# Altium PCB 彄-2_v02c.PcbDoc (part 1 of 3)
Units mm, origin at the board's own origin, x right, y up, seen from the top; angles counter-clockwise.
Board outline 115 x 70 mm, 4 copper layers (Top Layer, Mid-Layer 1, Mid-Layer 2, Bottom Layer), stack 1.49 mm thick; 312 components, 169 nets, 916 pads, 492 vias.
Unrouted connection lines stored in the file: 1.
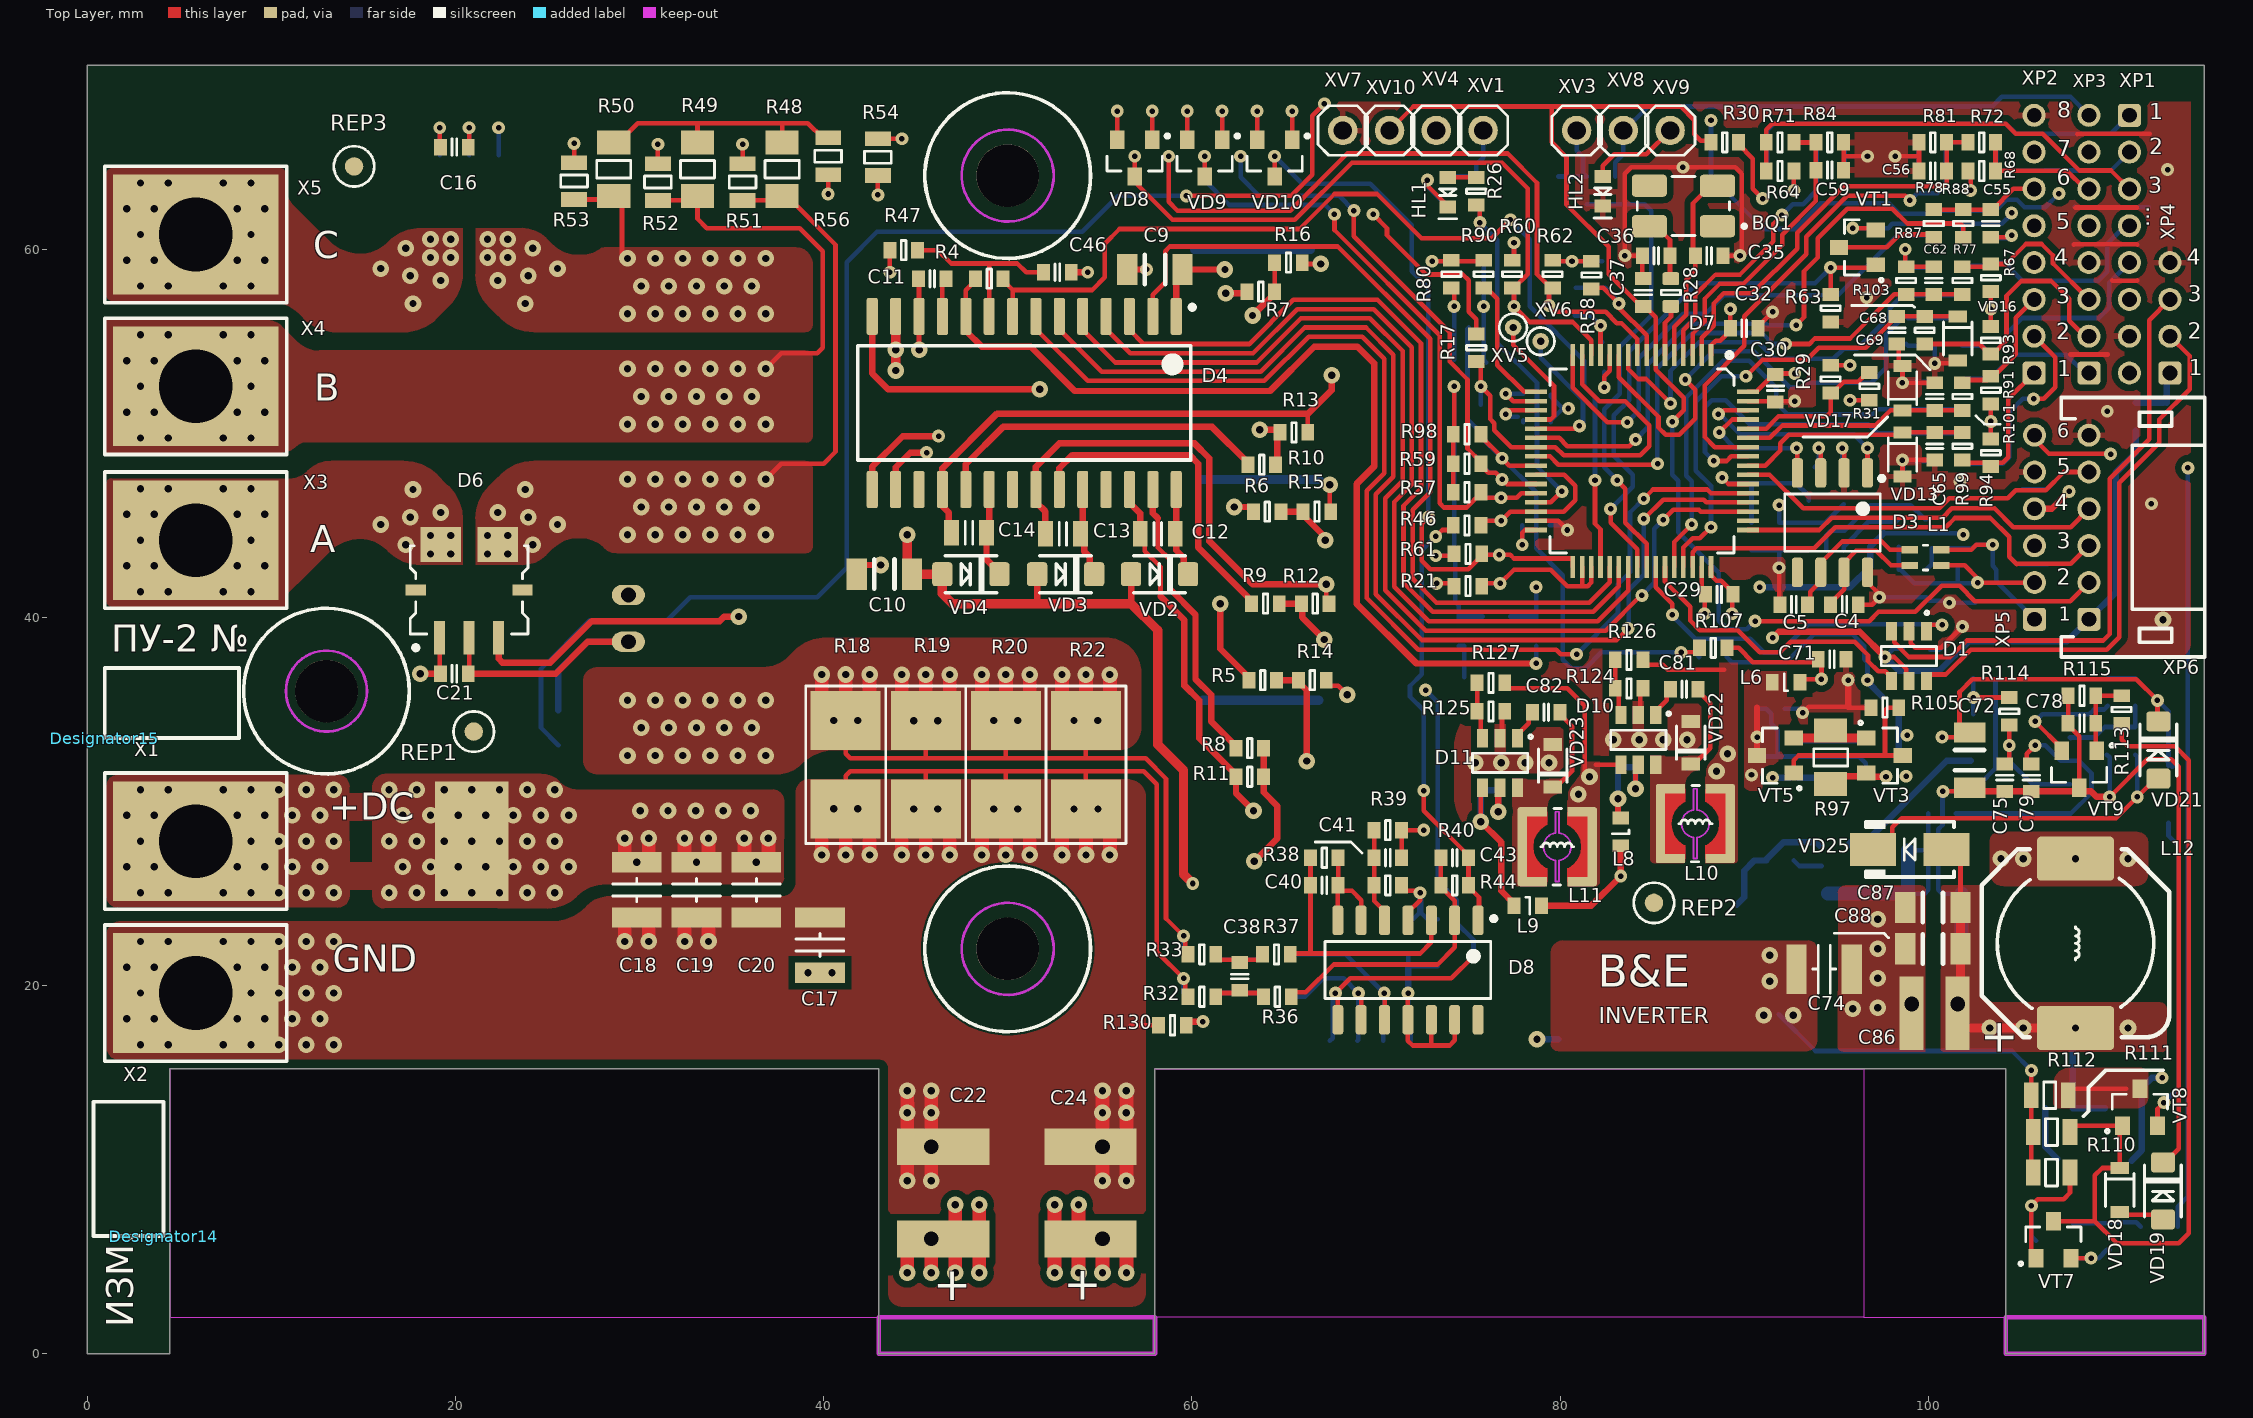
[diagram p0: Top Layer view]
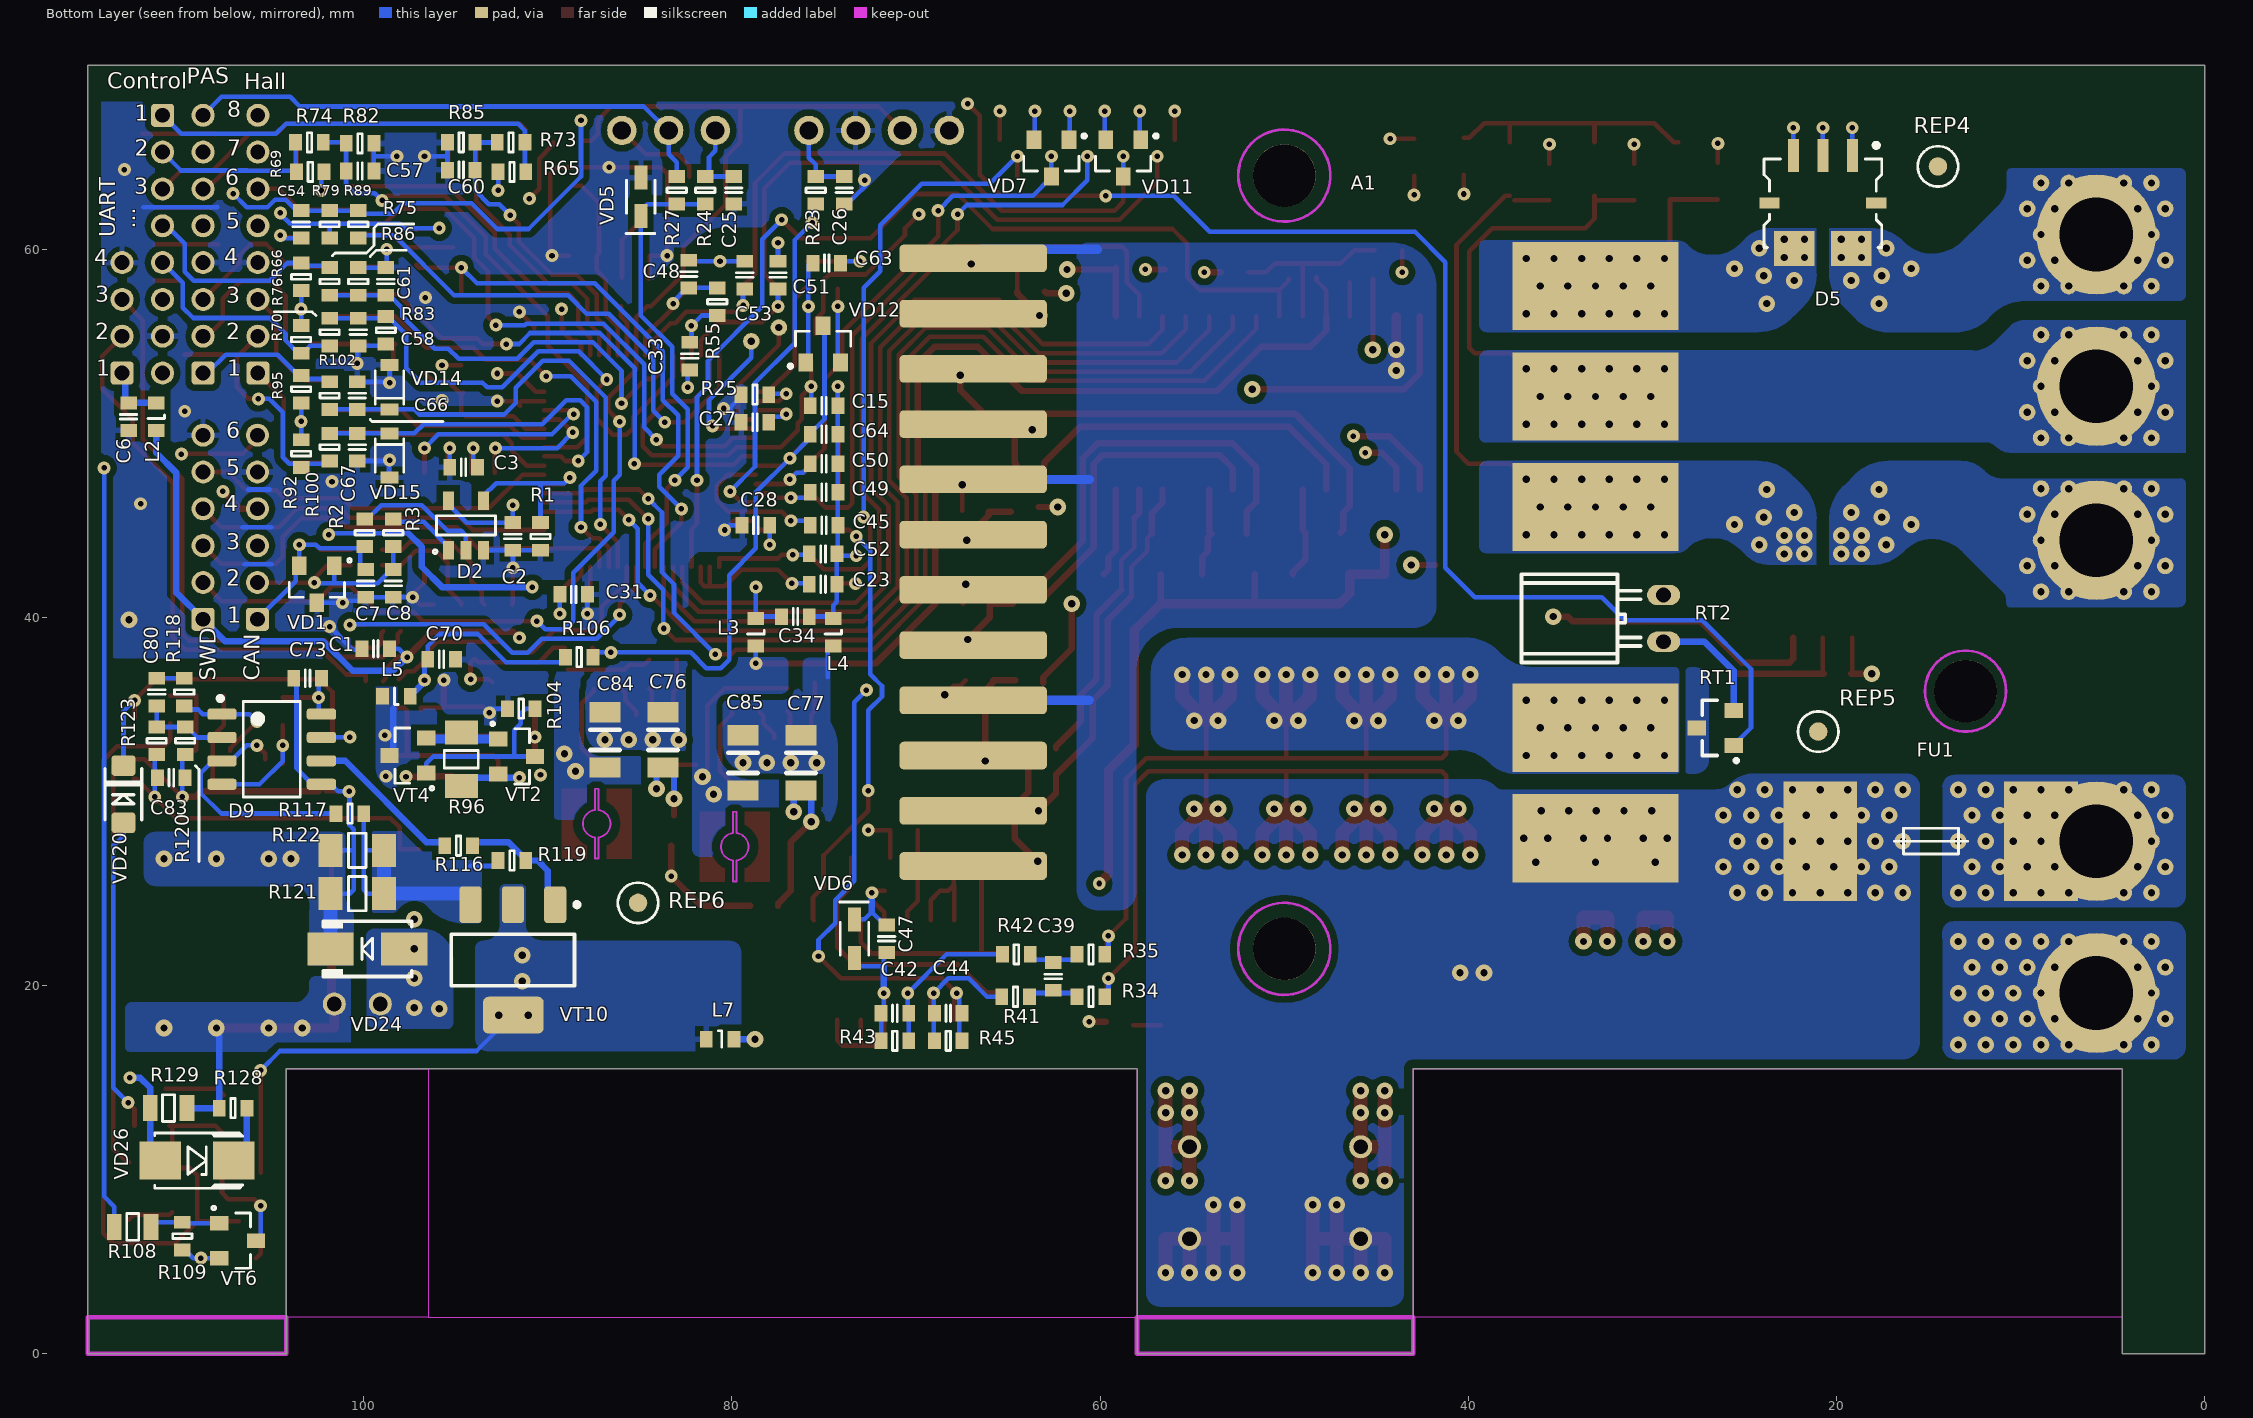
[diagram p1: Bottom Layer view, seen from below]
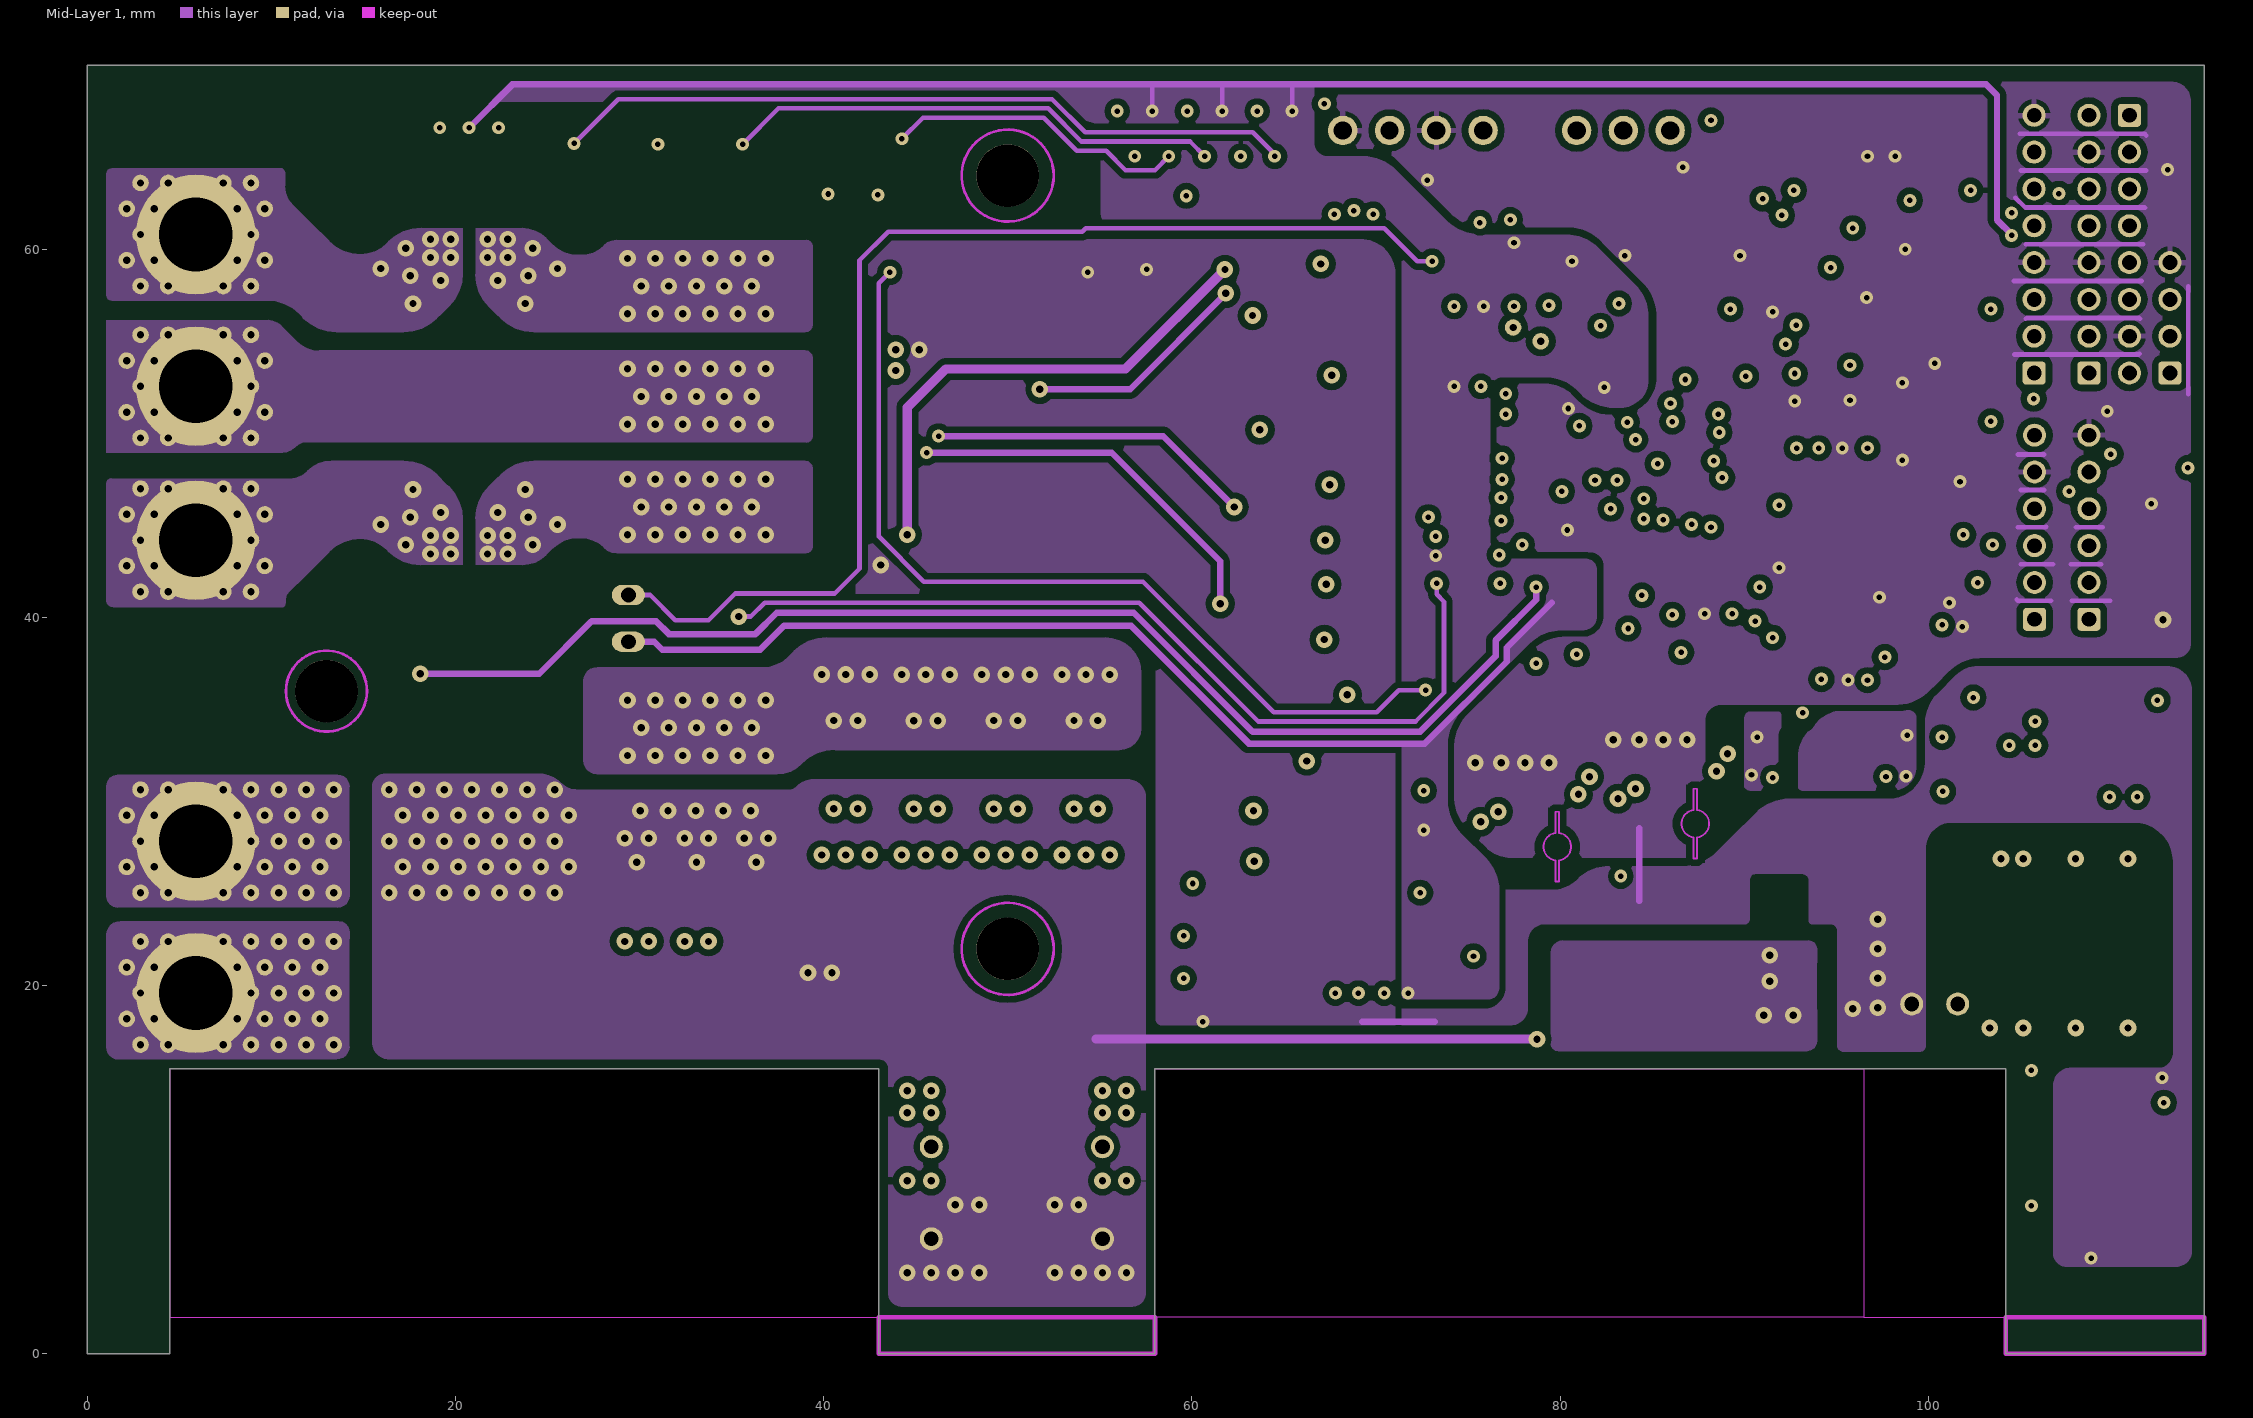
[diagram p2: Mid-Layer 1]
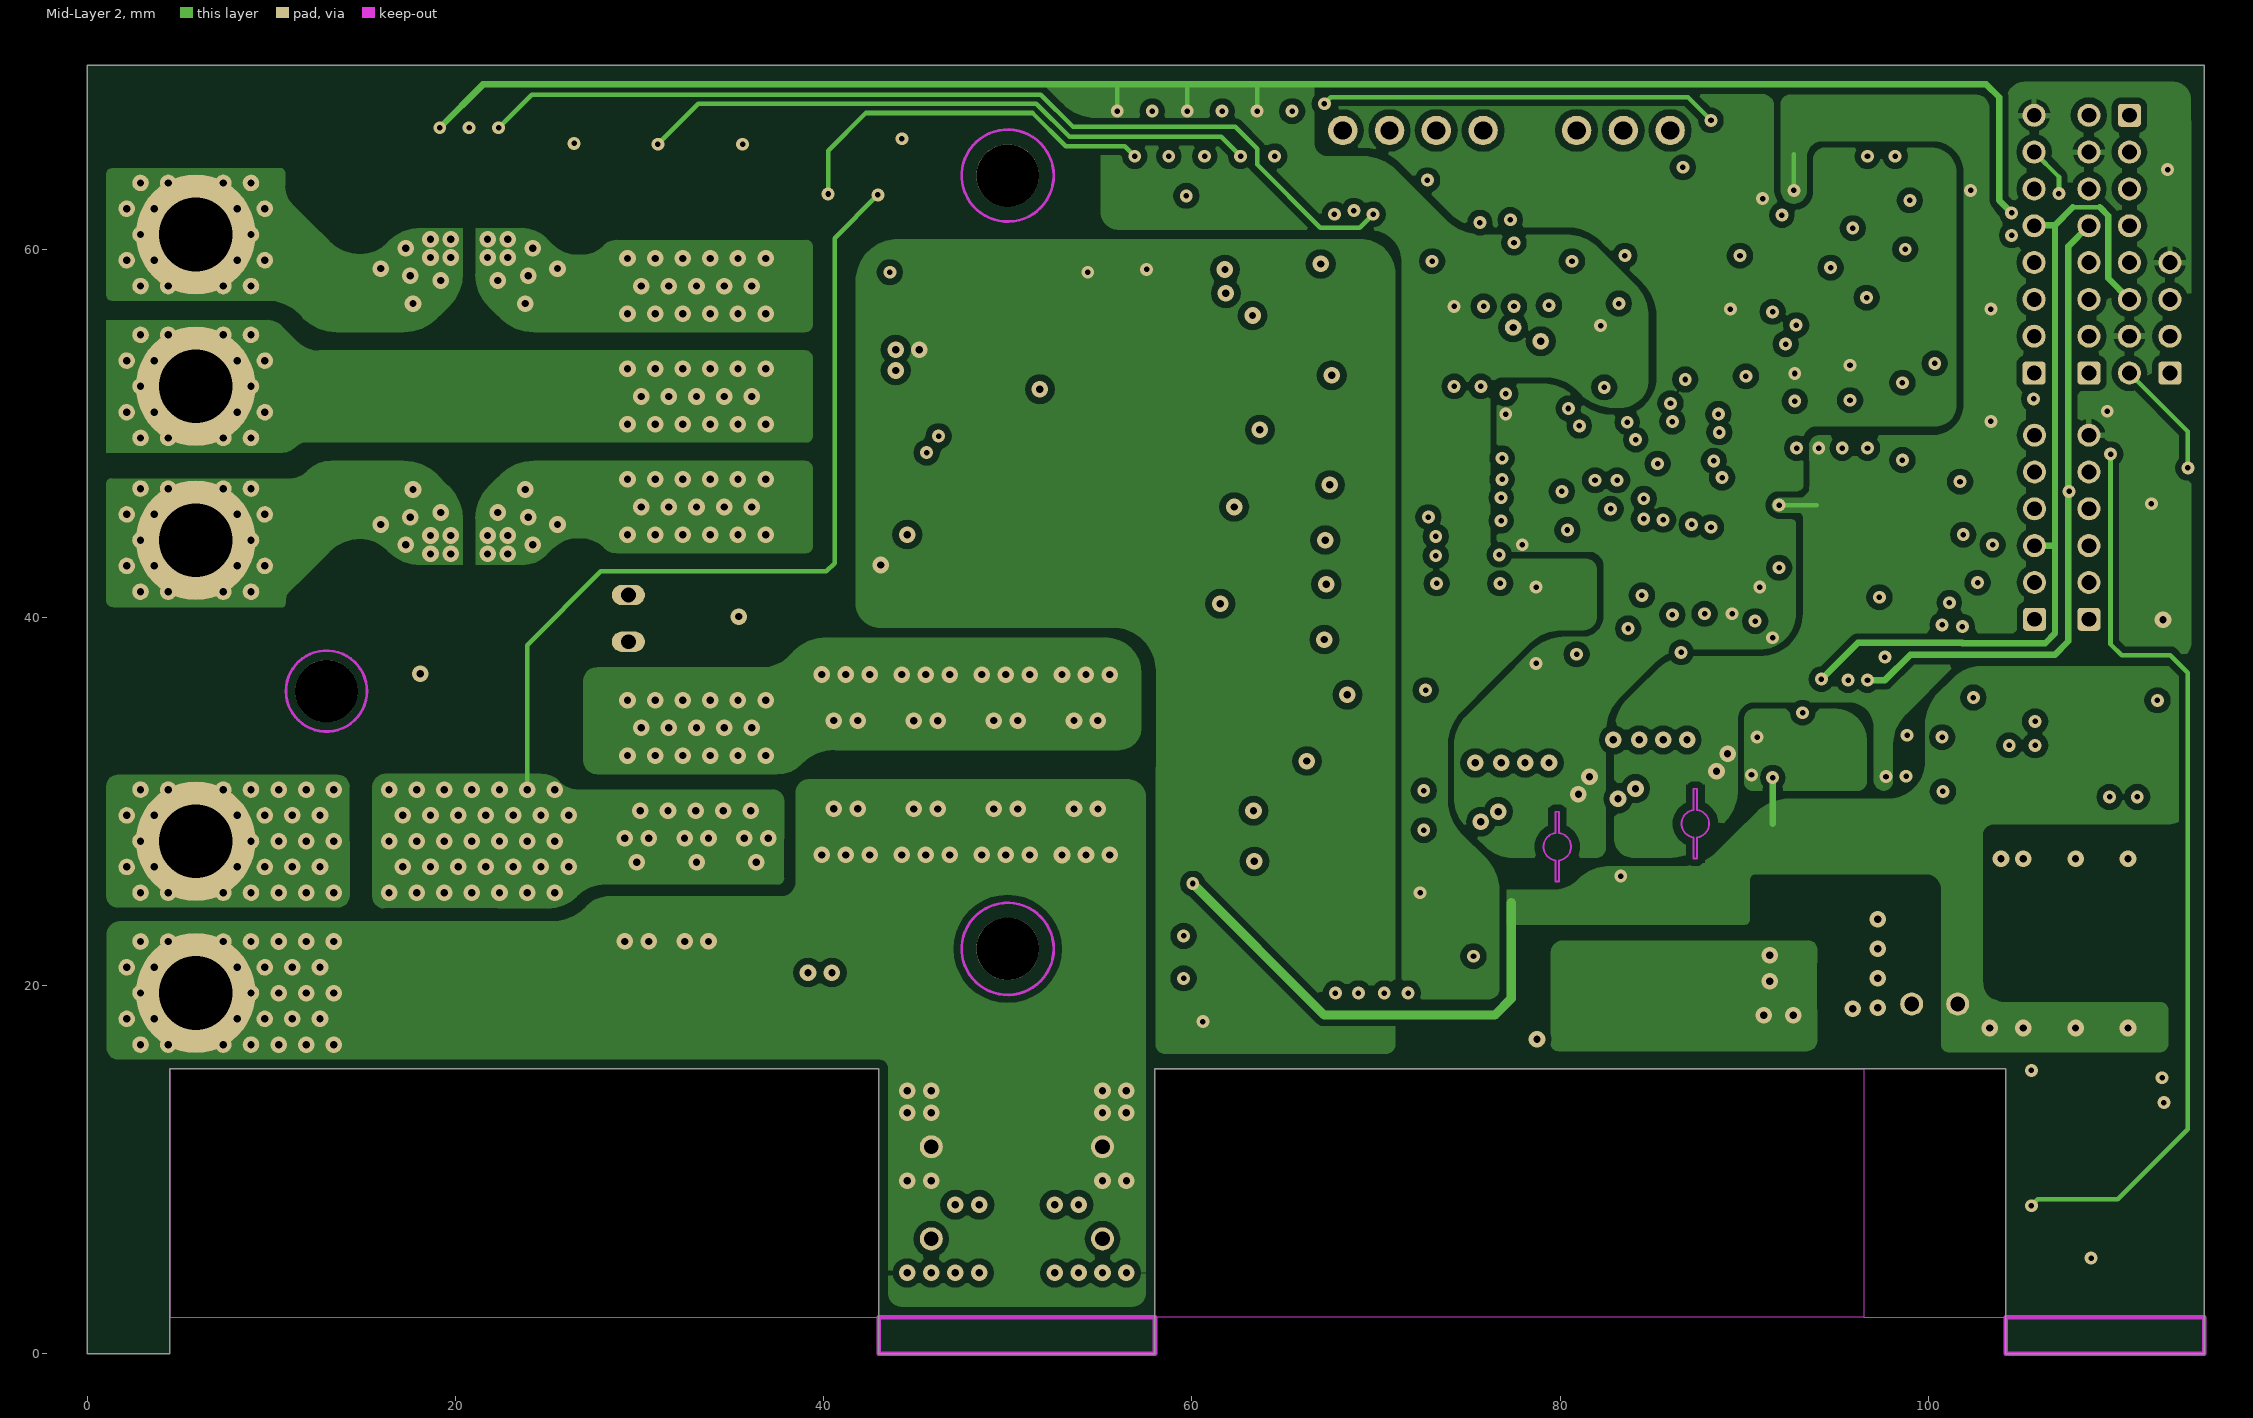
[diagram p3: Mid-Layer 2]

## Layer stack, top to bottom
Top Layer: signal copper 0.035
Dielectric: prepreg 0.32, FR-4, Dk 4.8
Mid-Layer 1: signal copper 0.035
Dielectric: core 0.71, FR-4, Dk 4.8
Mid-Layer 2: signal copper 0.035
Dielectric: prepreg 0.32, FR-4, Dk 4.8
Bottom Layer: signal copper 0.035

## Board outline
0,0 0,70 115,70 115,0 104.2,0 104.2,15.5 58,15.5 58,0 43,0 43,15.5 4.5,15.5 4.5,0

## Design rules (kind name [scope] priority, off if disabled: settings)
Clearance Clearance_2 [(InNetClass('HighVoltage'))] p1: gap=0.4
Clearance Clearance_1 [(IsRegion)] p2: gap=0.35
Clearance [All] p3: gap=0.24
ComponentClearance ComponentClearance_1 [(InComponentClass('Clearance0'))] p1: gap=0 collisioncheckmode=3 verticalgap=0 showdistances=FALSE
ComponentClearance [All] p2: gap=0.63 collisioncheckmode=3 verticalgap=0.63 showdistances=FALSE
FabricationTestPointUsage TestPointUsage [All] p1: valid=0 allowmultiple=FALSE
FabricationTestpoint Testpoint [All] p1: side=3 testpointundercomponent=TRUE minsize=1.016 maxsize=2.54 preferedsize=1.524 minholesize=0 maxholesize=1.016 preferedholesize=0.813 testpointgrid=0.025 allowsidetop=TRUE allowsidebottom=TRUE usegrid=TRUE gridtolerance=0
Height [All] p1: minheight=0 maxheight=30 prefheight=12.7
HoleSize [All] p1: absolutevalues=TRUE maxlimit=5 minlimit=0.3 maxpercent=80.000 minpercent=20.000
HoleToHoleClearance [All] p1: gap=0.4 allowstackedmicrovias=TRUE
MinimumSolderMaskSliver [All] p1: minsoldermaskwidth=0.2
PlaneClearance [All] p1: clearance=0.35
PlaneConnect [All] p1: planeconnectstyle=Relief reliefexpansion=1 reliefentries=4 reliefconductorwidth=0.35 reliefairgap=0.3
PolygonConnect PolygonConnect_1 [(InPadClass('Relief connect'))] p1: connectstyle=Relief reliefconductorwidth=0.3 reliefentries=4 polygonreliefangle="90 Angle"
PolygonConnect [All] p2: connectstyle=Direct reliefconductorwidth=0.35 reliefentries=4 polygonreliefangle="90 Angle"
RoomDefinition ПУ-2_v02_л02 [InComponentClass('ПУ-2_v02_л02')] p1: confinementstyle=ConfineIn formatcopy=TRUE lockcomponents=FALSE outline -85.8,-225.6 -35,-225.6 -35,-200.2 -85.8,-200.2
RoomDefinition VoltageMeas [InComponentClass('VoltageMeas')] p2: confinementstyle=ConfineIn formatcopy=TRUE lockcomponents=FALSE outline -85.8,-225.6 -35,-225.6 -35,-200.2 -85.8,-200.2
RoomDefinition "Power Wires" [InComponentClass('Power Wires')] p3: confinementstyle=ConfineIn formatcopy=TRUE lockcomponents=FALSE outline -85.8,-225.6 -35,-225.6 -35,-200.2 -85.8,-200.2
RoomDefinition Power [InComponentClass('Power')] p4: confinementstyle=ConfineIn formatcopy=TRUE lockcomponents=FALSE outline -85.8,-225.6 -35,-225.6 -35,-200.2 -85.8,-200.2
RoomDefinition OutVoltage [InComponentClass('OutVoltage')] p5: confinementstyle=ConfineIn formatcopy=TRUE lockcomponents=FALSE outline -85.8,-225.6 -35,-225.6 -35,-200.2 -85.8,-200.2
RoomDefinition MCU [InComponentClass('MCU')] p6: confinementstyle=ConfineIn formatcopy=TRUE lockcomponents=FALSE outline -85.8,-225.6 -35,-225.6 -35,-200.2 -85.8,-200.2
RoomDefinition Inputs [InComponentClass('Inputs')] p7: confinementstyle=ConfineIn formatcopy=TRUE lockcomponents=FALSE outline -85.8,-225.6 -35,-225.6 -35,-200.2 -85.8,-200.2
RoomDefinition Driver [InComponentClass('Driver')] p8: confinementstyle=ConfineIn formatcopy=TRUE lockcomponents=FALSE outline -85.8,-225.6 -35,-225.6 -35,-200.2 -85.8,-200.2
RoomDefinition CAN [InComponentClass('CAN')] p9: confinementstyle=ConfineIn formatcopy=TRUE lockcomponents=FALSE outline -85.8,-225.6 -35,-225.6 -35,-200.2 -85.8,-200.2
RoomDefinition 100-12 [InComponentClass('100-12')] p10: confinementstyle=ConfineIn formatcopy=TRUE lockcomponents=FALSE outline -85.8,-225.6 -35,-225.6 -35,-200.2 -85.8,-200.2
RoomDefinition 12-5 [InComponentClass('12-5')] p11: confinementstyle=ConfineIn formatcopy=TRUE lockcomponents=FALSE outline -85.8,-225.6 -35,-225.6 -35,-200.2 -85.8,-200.2
RoomDefinition 12-3V3 [InComponentClass('12-3V3')] p12: confinementstyle=ConfineIn formatcopy=TRUE lockcomponents=FALSE outline -85.8,-225.6 -35,-225.6 -35,-200.2 -85.8,-200.2
RoomDefinition CurrentMeas [InComponentClass('CurrentMeas')] p13: confinementstyle=ConfineIn formatcopy=TRUE lockcomponents=FALSE outline 58.949,16.05 76.85,16.05 76.85,13.8 58.949,13.8
RoutingCorners [All] p1: cornerstyle=45-Degree minsetback=2.5 maxsetback=2.5
RoutingLayers [All] p1: top layer_v5=TRUE mid layer 1_v5=FALSE mid layer 2_v5=TRUE bottom layer_v5=TRUE
RoutingVias [All] p1: holewidth=0.3 width=0.7 viastyle="Through Hole" minholewidth=0.3 minwidth=0.7 maxholewidth=0.8 maxwidth=1.5
SilkToSilkClearance [All] p1: silktosilkclearance=0.18
SilkscreenOverComponentPads [IsPad] p1: minsilkscreentomaskgap=0.18
SolderMaskExpansion [All] p1: expansion=0.08
Width [All] p1: maxlimit=8 minlimit=0.22 preferedwidth=0.25
15 further rules are at their usual default settings.

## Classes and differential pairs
component class VoltageMeas: C48 C49 C50 C51 C52 C53 C64 R48 R49 R50 R51 R52 R53 R54 R55 R56 R57 R58 R59 R60 R61 R62 R98 R106 R107 R108 R110 R111 VD7 VD8 VD9 VD10 VD11 VD12
component class OutVoltage: C70 C71 R96 R97 R104 R105 VT1 VT2 VT3 VT4 VT5
component class Power: A1 C16 C17 C18 C19 C20 C21 C22 C24 D5 D6 R18 R19 R20 R22
component class Inputs: C54 C55 C56 C57 C58 C59 C60 C61 C62 C63 C65 C66 C67 C68 C69 R63 R64 R65 R66 R67 R68 R69 R70 R71 R72 R73 R74 R75 R76 R77 R78 R79 R80 R81 R82 R83 R84 R85 R86 R87 R88 R89 R90 R91 R92 R93 R94 R95 R99 R100 R101 R102 R103 R113 R115 RT1 RT2 VD13 VD14 VD15 VD16 VD17
component class Driver: C9 C10 C11 C12 C13 C14 R4 R5 R6 R7 R8 R9 R10 R11 R12 R13 R14 R15 R16 R128 R130 VD2 VD3 VD4
component class "Power Wires": X1 X2 X3 X4 X5
component class CurrentMeas: C38 C39 C40 C41 C42 C43 C44 C45 C46 C47 D8 R32 R33 R34 R35 R36 R37 R38 R39 R40 R41 R42 R43 R44 R45 R46 R47 VD6
component class 100-12: C72 C73 C74 C75 C78 C79 C80 C83 C86 C87 C88 D9 L7 L12 R109 R112 R114 R116 R117 R118 R119 R120 R121 R122 R123 R129 VD18 VD19 VD20 VD21 VD24 VD25 VT9 VT10
component class CAN: C1 C2 C3 C4 C5 C6 C7 C8 C151 C152 C155 C157 C158 C159 D1 D2 D3 D25 D27 L1 L20 R1 R2 R3 R192 R194 R195 VD1
pad class "Relief connect": C1-1 C1-2 C2-1 C2-2 C3-1 C3-2 C4-1 C4-2 C5-1 C5-2 C6-1 C6-2 C7-1 C7-2 C8-1 C8-2 C25-1 C25-2 C26-1 C26-2 C27-1 C27-2 C28-1 C28-2 C29-1 C29-2 C30-1 C30-2 C31-1 C31-2 C32-1 C32-2 C33-1 C33-2 C35-1 C35-2 C36-1 C36-2 C37-1 C37-2 C38-1 C38-2 C56-1 C56-2 C57-1 C57-2 C58-1 C58-2 C59-1 C59-2 C60-1 C60-2 C61-1 C61-2 C62-1 C62-2 C64-1 C64-2 C65-1 C65-2 C66-1 C66-2 C67-1 C67-2 C68-1 C68-2 C69-1 C69-2 C70-1 C70-2 C71-1 C71-2 D2-1 D2-2 D2-3 D2-4 D2-5 D3-1 D3-2 D3-3 D3-4 D3-5 D3-6 D3-7 D3-8 HL1-1 HL1-2 HL2-1 HL2-2 L7-1 L7-2 R1-1 R1-2 R31-1 R31-2 R63-1 R63-2 R75-1 R75-2 R76-1 R76-2 R78-1 R78-2 R79-1 R79-2 R80-1 R80-2 R81-1 R81-2 R82-1 R82-2 R83-1 R83-2 R84-1 R84-2 R85-1 R85-2 R86-1 R86-2 R87-1 R87-2 R98-1 R98-2 R99-1 R99-2 R104-1 R104-2 R105-1 R105-2 R117-1 R117-2 R118-1 R118-2 R124-1 R124-2 R125-1 R125-2 VD1-1 VD1-2 VD1-3 VD5-1 VD5-2 VD11-1 VD11-2 VD13-1 VD13-2 VD14-1 VD14-2 VD15-1 VD15-2 VD16-1 VD16-2 VD17-1 VD17-2 XP1-1 XP1-2 XP1-3 XP1-4 XP1-5 XP1-6 XP1-7 XP1-8 XP2-1 XP2-2 XP2-3 XP2-4 XP2-5 XP2-6 XP2-7 XP2-8 XP3-1 XP3-2 XP3-3 XP3-4 XP3-5 XP3-6 XP3-7 XP3-8 XP4-1 XP4-2 XP4-3 XP4-4 XP5-1 XP5-2 XP5-3 XP5-4 XP5-5 XP5-6 XP6-1 XP6-2 XP6-3 XP6-4 XP6-5 XP6-6 XV1-1 XV3-1 XV4-1 XV5-1 XV6-1 XV7-1 XV8-1 XV9-1 XV10-1
polygon class Thermal: GND
polygon class Input24V: Input+24V InputGND24
polygon class PowOut24V: Out+24V OutGND24
polygon class PowOut12V: PowOut+12V PowOut-12V
component class MCU: BQ1 C15 C23 C25 C26 C27 C28 C29 C30 C31 C32 C33 C34 C35 C36 C37 D7 HL1 HL2 HL3 R17 R21 R23 R24 R25 R26 R27 R28 R29 R30 R31 SB1 TP5 TP6 TP10 VD5 XP8 XV1 XV3 XV4 XV7 XV8 XV9 XV10
component class 12-3V3: C77 C82 C85 D11 L9 L11 R125 R127 VD23
component class 12-5: C76 C81 C84 D10 L8 L10 R124 R126 VD22
component class ПУ-2_v02_л02: A1 C9 C10 C11 C12 C13 C14 C15 C16 C17 C18 C19 C20 C21 C22 C23 C24 D4 D5 D6 R4 R5 R6 R7 R8 R9 R10 R11 R12 R13 R14 R15 R16 R17 R18 R19 R20 R21 R22 VD2 VD3 VD4

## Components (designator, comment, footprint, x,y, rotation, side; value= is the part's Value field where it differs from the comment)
A1 "MTI85W100GC-SMD" ISOPLUS-DIL 50,43 r0 bottom locked
BQ1 "MJ-8.000-12-20/20I" MJ-series 88.55,61.25 r0 top
C1 "CL10B104KB8NNNC" 0603 100.1,38.3 r180 bottom
C2 "CL10B104KB8NNNC" 0603 91.9,43.65 r90 bottom
C3 "CL10B104KB8NNNC" 0603 95.33,48.15 r180 bottom
C4 "CL10C120JB8NNNC" 0603 96.2,40.7 r180 top
C5 "CL10C120JB8NNNC" 0603 91.95,40.7 r0 top
C6 "CL10A106MQ8NNNC" 0603 112.775,51.65 r270 bottom
C7 "CL10C120JB8NNNC" 0603 99.9,41.1 r90 bottom
C8 "CL10C120JB8NNNC" 0603 98.4,41.1 r90 bottom
C9 "CL31A106KAHNNNE" 1206 56.5,58.9 r0 top
C10 "CL31A106KAHNNNE" 1206 41.8,42.35 r0 top
C11 "CL10C102JB8NNNC" 0603 45.15,58.4 r0 top
C12 "CL21A475KAQ" 0805 57.2,44.55 r0 top
C13 "CL21A475KAQ" 0805 52.05,44.55 r0 top
C14 "CL21A475KAQ" 0805 46.95,44.6 r0 top
C15 "CL10B103KB8NNNC" 0603 74.25,51.5 r0 bottom
C16 "CL10B104KB8NNNC" 0603 20.7,65.55 r180 top
C17 "CL32B225KCJSNNE" 1210 39.802,23.705 r270 top
C18 "CL32B225KCJSNNE" 1210 29.851,23.701 r90 top
C19 "CL32B225KCJSNNE" 1210 33.101,23.701 r90 top
C20 "CL32B225KCJSNNE" 1210 36.351,23.701 r90 top
C21 "CL10B104KB8NNNC" 0603 20.7,36.95 r180 top
C22 "EKZN101ELL391MK35S" 12.5x35s#1 46.5,6.25 r0 top
C23 "CL10B103KB8NNNC" 0603 74.3,41.8 r0 bottom
C24 "EKZN101ELL391MK35S" 12.5x35s#2 54.5,6.25 r180 top
C25 "CL10B103KB8NNNC" 0603 79.9,62.45 r90 bottom
C26 "CL10B103KB8NNNC" 0603 73.9,62.45 r90 bottom
C27 "CL10B104KB8NNNC" 0603 79.5,50.6 r180 bottom
C28 "CL10B104KB8NNNC" 0603 79.45,45 r180 bottom
C29 "CL10B104KB8NNNC" 0603 87.9,41.25 r0 top
C30 "CL10B104KB8NNNC" 0603 91.7,51.7 r90 top
C31 "CL10A106MQ8NNNC" 0603 87.85,41.25 r0 bottom
C32 "CL10A106MQ8NNNC" 0603 90.75,55.7 r180 top
C33 "CL10B104KB8NNNC" 0603 82.3,53.45 r90 bottom
C34 "CL10A106MQ8NNNC" 0603 75.8,40.05 r0 bottom
C35 "CL10C120JB8NNNC" 0603 88.85,59.65 r180 top
C36 "CL10C120JB8NNNC" 0603 84.475,59.65 r0 top
C37 "CL10B104KB8NNNC" 0603 84.525,58.4 r270 top
C38 "CL10B332KB8NNNC" 0603 62.6,21.25 r270 top
C39 "CL10B332KB8NNNC" 0603 62.55,21.25 r270 bottom
C40 "CL10C270JB8NNNC" 0603 66.45,25.45 r0 top
C41 "CL10B104KB8NNNC" 0603 69.9,26.95 r0 top
C42 "CL10C331JB8NNNC" 0603 70.4,18.5 r0 bottom
C43 "CL10C270JB8NNNC" 0603 75.03,26.95 r180 top
C44 "CL10C331JB8NNNC" 0603 69,18.5 r180 bottom
C45 "CL10C102JB8NNNC" 0603 74.25,45 r0 bottom
C46 "CL10C102JB8NNNC" 0603 53.45,58.75 r180 top
C47 "CL10B104KB8NNNC" 0603 71.6,21.8 r90 bottom
C48 "CL10B103KB8NNNC" 0603 82.35,57.9 r90 bottom
C49 "CL10B103KB8NNNC" 0603 75.75,46.8 r180 bottom
C50 "CL10B103KB8NNNC" 0603 75.75,48.35 r180 bottom
C51 "CL10B103KB8NNNC" 0603 77.5,57.85 r90 bottom
C52 "CL10B103KB8NNNC" 0603 75.8,43.45 r180 bottom
C53 "CL10B103KB8NNNC" 0603 79.3,57.85 r90 bottom
C54 "CL10B103KB8NNNC" 0603 103.4,60.6 r90 bottom
C55 "CL10B103KB8NNNC" 0603 103.4,60.65 r90 top
C56 "CL10B103KB8NNNC" 0603 99.5,64.25 r0 top
C57 "CL10B103KB8NNNC" 0603 99.45,64.25 r0 bottom
C58 "CL10B103KB8NNNC" 0603 100.3,54.75 r90 bottom
C59 "CL10B103KB8NNNC" 0603 95.4,64.3 r180 top
C60 "CL10B103KB8NNNC" 0603 95.45,64.3 r180 bottom
C61 "CL10B103KB8NNNC" 0603 98.8,59 r270 bottom
C62 "CL10B103KB8NNNC" 0603 100.3,59.05 r270 top
C63 "CL10B103KB8NNNC" 0603 75.6,59.25 r180 bottom
C64 "CL10B103KB8NNNC" 0603 75.75,49.95 r180 bottom
C65 "CL10C331JB8NNNC" 0603 100.35,48.55 r90 top
C66 "CL10C331JB8NNNC" 0603 100.35,52.8 r270 bottom
C67 "CL10C331JB8NNNC" 0603 100.35,48.5 r90 bottom
C68 "CL10C331JB8NNNC" 0603 98.3,54.85 r90 top
C69 "CL10C331JB8NNNC" 0603 100.35,52.75 r270 top
C70 "CL10B104KB8NNNC" 0603 95.025,37.725 r0 bottom
C71 "CL10B104KB8NNNC" 0603 95.525,37.725 r180 top
C72 "CL31A106KAHNNNE" 1206 102.25,30.75 r90 top
C73 "CL10B104KB8NNNC" 0603 102.3,36.7 r0 bottom
C74 "CL32B225KCJSNNE" 1210 95.85,20.9 r180 top
C75 "CL10C102JB8NNNC" 0603 104.15,30.55 r90 top
C76 "CL31A106KAHNNNE" 1206 83.75,34.85 r270 bottom
C77 "CL31A106KAHNNNE" 1206 76.25,33.6 r270 bottom
C78 "CL10A106MQ8NNNC" 0603 109.1,34.25 r180 top
C79 "CL10C331JB8NNNC" 0603 105.6,30.55 r90 top
C80 "CL10C102JB8NNNC" 0603 111.25,35.2 r90 bottom
C81 "CL10B103KB8NNNC" 0603 87.5,36.1 r180 top
C82 "CL10B103KB8NNNC" 0603 80,34.85 r180 top
C83 "CL10B104KB8NNNC" 0603 111.2,31.3 r180 bottom
C84 "CL31A226MOCLNNC" 1206 86.9,34.85 r270 bottom
C85 "CL31A226MOCLNNC" 1206 79.4,33.6 r270 bottom
C86 "UHE1E101MED" 6.3x11s 100.35,18.5 r90 top
C87 "CL31A106KAHNNNE" 1206 98.75,24.25 r0 top
C88 "CL31A106KAHNNNE" 1206 98.75,22 r0 top
D1 "SN74LVC2G34DBVR" SOT23-6 99.9,39.25 r270 top
D2 "TS5A3167DBVR" SOT23-5 95.4,43.65 r90 bottom
D3 "SN65HVD1050" SOIC-8 96.7,47.85 r270 top
D4 "FAN73895MX" SOIC-28 50.9,51.65 r270 top
D5 "ACS781KLRTR-150B-T" "LR 7-pin PSOF" 20.75,62.5 r0 bottom
D6 "ACS781KLRTR-150B-T" "LR 7-pin PSOF" 20.75,41.5 r0 top
D7 "STM32F303RET6" LQFP-64 84.45,48.5 r270 top locked
D8 "AD8604ARZ" SOIC-14N 75.55,23.55 r270 top
D9 "UC2843BG-S08-R" SOP-8 107.7,34.75 r180 bottom
D10 "AP3211KTR-G1" SOT23-6 85.2,34.7 r270 top
D11 "AP3211KTR-G1" SOT23-6 77.7,33.45 r270 top
Designator14 "Comment" IZM1 4.15,6.4 r90 top
Designator15 "Comment" IZM1 0.95,33.45 r0 top
FU1 "100A" 100A_05mmCUfoil 8.9,27.85 r0 bottom
HL1 "BL-HUE36A-AV-TRB" HL0603 73.9,62.3 r90 top
HL2 "BL-HGF36A-AV-TRB" HL0603 82.325,62.35 r90 top
L1 "DLW21SN371SQ2L" DLW21S 99.85,43.25 r0 top
L2 "BLM18PG331SN1D" BLM18 111.275,50.15 r90 bottom
L3 "BLM18RK601SN1" BLM18 78.7,38.45 r90 bottom
L4 "BLM18PG331SN1D" BLM18 74.5,38.45 r90 bottom
L5 "BLM18PG331SN1D" BLM18 98.975,35.725 r180 bottom
L6 "BLM18PG331SN1D" BLM18 91.525,36.475 r0 top
L7 "BLM18PG331SN1D" BLM18 79.9,17.1 r0 bottom
L8 "BLM18PG331SN1D" BLM18 83.3,27.6 r90 top
L9 "BLM18PG331SN1D" BLM18 79,24.35 r180 top
L10 "SH30184R7YL" SH3018 87.35,28.8 r0 top
L11 "SH30184R7YL" SH3018 79.85,27.55 r0 top
L12 "SRR1050A-221Y" SRR1050A 108,22.3 r270 top
R1 "RC0603FR-0710KL" RC0603#1 90.4,45.15 r270 bottom
R2 "RC0603FR-0762RL" RC0603#1 99.95,45.35 r270 bottom
R3 "RC0603FR-0762RL" RC0603#1 98.4,45.35 r270 bottom
R4 "RC0603FR-0710KL" RC0603#1 48.25,58.4 r0 top
R5 "RC0603FR-0762RL" RC0603#1 64.6,36.6 r180 top
R6 "RC0603FR-0762RL" RC0603#1 64.85,45.75 r180 top
R7 "RC0603FR-0762RL" RC0603#1 64.5,57.7 r180 top
R8 "RC0603FR-0762RL" RC0603#1 63.9,32.9 r180 top
R9 "RC0603FR-0762RL" RC0603#1 64.75,40.75 r180 top
R10 "RC0603FR-0762RL" RC0603#1 64.55,48.3 r180 top
R11 "RC0603FR-0710KL" RC0603#1 62.4,31.35 r0 top
R12 "RC0603FR-0710KL" RC0603#1 67.45,40.75 r180 top
R13 "RC0603FR-0710KL" RC0603#1 66.3,50.05 r180 top
R14 "RC0603FR-0710KL" RC0603#1 65.8,36.6 r0 top
R15 "RC0603FR-0710KL" RC0603#1 66.05,45.75 r0 top
R16 "RC0603FR-0710KL" RC0603#1 64.5,59.275 r0 top
R17 "RC0603FR-07220RL" RC0603#1 75.45,53.9 r90 top
R18 "CRE2512-FZ-R002E-3" CRE2512 41.201,34.401 r270 top
R19 "CRE2512-FZ-R002E-3" CRE2512 45.551,34.401 r270 top
R20 "CRE2512-FZ-R002E-3" CRE2512 49.902,34.4 r270 top
R21 "RC0603FR-07220RL" RC0603#1 75.75,41.7 r180 top
R22 "CRE2512-FZ-R002E-3" CRE2512 54.25,34.4 r270 top
R23 "RC0603FR-073KL" RC0603#1 75.45,62.45 r90 bottom
R24 "RC0603FR-073KL" RC0603#1 81.45,62.45 r90 bottom
R25 "RC0603JR-070RL" RC0603#1 78,52.1 r0 bottom
R26 "RC0603FR-071KL" RC0603#1 75.45,63.9 r270 top
R27 "RC0603FR-07390L" RC0603#1 83,63.95 r270 bottom
R28 "RC0603FR-07220RL" RC0603#2 86.025,58.4 r270 top
R29 "RC0603JR-070RL" RC0603#1 94.7,52.2 r90 top
R30 "RC0603FR-07100KL" RC0603#1 88.2,65.8 r0 top
R31 "RC0603FR-0710KL" RC0603#1 96.8,53.3 r270 top
R32 "RC0603FR-07100RL" RC0603#1 59.8,19.4 r0 top
R33 "RC0603FR-07100RL" RC0603#1 59.8,21.7 r0 top
R34 "RC0603FR-07100RL" RC0603#1 59.75,19.4 r0 bottom
R35 "RC0603FR-07100RL" RC0603#1 59.75,21.7 r0 bottom
R36 "RC0603FR-07100RL" RC0603#1 63.9,19.4 r0 top
R37 "RC0603FR-07100RL" RC0603#1 63.85,21.7 r0 top
R38 "RC0603FR-073K9L" RC0603#1 67.95,26.95 r180 top
R39 "RC0603FR-0710KL" RC0603#1 71.4,28.45 r180 top
R40 "RC0603FR-0710KL" RC0603#1 71.4,25.45 r180 top
R41 "RC0603FR-07100RL" RC0603#1 63.85,19.4 r0 bottom
R42 "RC0603FR-07100RL" RC0603#1 63.8,21.7 r0 bottom
R43 "RC0603FR-071K2L" RC0603#1 71.9,17 r180 bottom
R44 "RC0603FR-073K9L" RC0603#1 73.53,25.45 r0 top
R45 "RC0603FR-071K2L" RC0603#1 69,17 r180 bottom
R46 "RC0603FR-07390RL" RC0603#1 74.2,45 r0 top
R47 "RC0603FR-07390RL" RC0603#1 43.6,59.95 r0 top
R48 "RC1206FR-0715KL" RC1206 37.75,62.9 r90 top
R49 "RC1206FR-0715KL" RC1206 33.15,62.9 r90 top
R50 "RC1206FR-0715KL" RC1206 28.6,62.9 r90 top
R51 "RC0805FR-07200KL" RC0805 35.6,62.65 r90 top
R52 "RC0805FR-07200KL" RC0805 31,62.65 r90 top
R53 "RC0805FR-07200KL" RC0805 26.45,62.7 r90 top
R54 "RC0805FR-07200KL" RC0805 42.95,64 r90 top
R55 "RC0603FR-071KL" RC0603#1 80.8,57.9 r270 bottom
R56 "RC0805FR-07200KL" RC0805 40.25,66.05 r270 top
R57 "RC0603FR-076K8L" RC0603#1 74.2,46.8 r0 top
R58 "RC0603FR-076K8L" RC0603#1 81.7,59.35 r270 top
R59 "RC0603FR-076K8L" RC0603#1 74.2,48.35 r0 top
R60 "RC0603FR-076K8L" RC0603#1 77.4,59.4 r270 top
R61 "RC0603FR-076K8L" RC0603#1 74.25,43.45 r0 top
R62 "RC0603FR-076K8L" RC0603#1 79.6,59.4 r270 top
R63 "RC0603FR-0710KL" RC0603#1 94.7,56.05 r90 top
R64 "RC0603FR-073KL" RC0603#1 92.7,64.25 r180 top
R65 "RC0603FR-073KL" RC0603#1 92.7,64.2 r180 bottom
R66 "RC0603FR-0710KL" RC0603#1 103.4,57.75 r90 bottom
R67 "RC0603FR-0710KL" RC0603#1 103.4,57.7 r90 top
R68 "RC0603FR-073KL" RC0603#1 102.15,64.25 r0 top
R69 "RC0603FR-073KL" RC0603#1 102.15,64.2 r0 bottom
R70 "RC0603FR-0710KL" RC0603#1 103.4,55.85 r270 bottom
R71 "RC0603FR-0752K3L" RC0603#1 91.2,65.8 r0 top
R72 "RC0603FR-0752K3L" RC0603#1 103.65,65.8 r180 top
R73 "RC0603FR-0752K3L" RC0603#1 91.25,65.8 r0 bottom
R74 "RC0603FR-0752K3L" RC0603#1 103.7,65.8 r180 bottom
R75 "RC0603FR-0752K3L" RC0603#1 101.85,59 r270 bottom
R76 "RC0603FR-0752K3L" RC0603#1 101.85,54.75 r90 bottom
R77 "RC0603FR-0752K3L" RC0603#1 101.85,59.05 r270 top
R78 "RC0603FR-071KL" RC0603#1 100.3,62.15 r270 top
R79 "RC0603FR-071KL" RC0603#1 101.85,62.1 r270 bottom
R80 "RC0603FR-071KL" RC0603#1 74.1,59.4 r270 top
R81 "RC0603FR-07100KL" RC0603#1 99.5,65.8 r0 top
R82 "RC0603FR-07100KL" RC0603#1 99.45,65.75 r0 bottom
R83 "RC0603FR-07100KL" RC0603#1 98.8,54.85 r90 bottom
R84 "RC0603FR-07100KL" RC0603#1 95.4,65.8 r180 top
R85 "RC0603FR-07100KL" RC0603#1 95.45,65.8 r180 bottom
R86 "RC0603FR-07100KL" RC0603#1 100.3,59 r270 bottom
R87 "RC0603FR-07100KL" RC0603#1 98.8,59.05 r270 top
R88 "RC0603FR-07100RL" RC0603#1 101.9,60.65 r90 top
R89 "RC0603FR-07100RL" RC0603#1 100.3,60.6 r90 bottom
R90 "RC0603FR-07100RL" RC0603#1 75.85,57.9 r90 top
R91 "RC0603FR-071K2L" RC0603#1 103.4,51.6 r90 top
R92 "RC0603FR-071K2L" RC0603#1 103.4,49.65 r270 bottom
R93 "RC0603FR-071K2L" RC0603#1 103.4,55.8 r270 top
R94 "RC0603FR-071K2L" RC0603#1 103.4,49.7 r270 top
R95 "RC0603FR-071K2L" RC0603#1 103.4,51.65 r90 bottom
R96 "RC1206JR-072RL" RC1206 94.7,30.85 r90 bottom
R97 "RC1206JR-072RL" RC1206 94.7,30.95 r90 top
R98 "RC0603FR-076K8L" RC0603#1 74.2,49.95 r0 top
R99 "RC0603FR-073KL" RC0603#1 101.85,50.05 r270 top
R100 "RC0603FR-073KL" RC0603#1 101.85,50 r270 bottom
R101 "RC0603FR-073KL" RC0603#1 101.85,51.25 r90 top
R102 "RC0603FR-073KL" RC0603#1 101.85,51.3 r90 bottom
R103 "RC0603FR-073KL" RC0603#1 99.8,56.35 r270 top
R104 "RC0603FR-0710KL" RC0603#1 92.2,35.05 r180 bottom
R105 "RC0603FR-073KL" RC0603#1 96.9,35.1 r0 top
R106 "RC0603FR-0727KL" RC0603#1 87.55,37.85 r0 bottom
R107 "RC0603FR-0727KL" RC0603#1 87.575,38.35 r0 top
R108 "RC0805FR-07200KL" RC0805 111.55,6.9 r0 bottom
R109 "RC0603FR-0710KL" RC0603#1 109.85,5.65 r90 bottom
R110 "RC0805FR-07200KL" RC0805 107.7,9.85 r180 top
R111 "RC0805FR-07200KL" RC0805 107.7,12.05 r180 top
R112 "RC0805FR-072K7L" RC0805 105.6,14.05 r0 top
R113 "RC0603FR-07100KL" RC0603#1 110.5,35.75 r270 top
R114 "RC0603FR-076K8L" RC0603#1 104.4,35.65 r270 top
R115 "RC0603FR-07100KL" RC0603#1 109.1,35.75 r180 top
R116 "RC0603FR-0762RL" RC0603#1 94.1,27.6 r0 bottom
R117 "RC0603FR-07220RL" RC0603#1 100,29.35 r0 bottom
R118 "RC0603FR-0710KL" RC0603#1 109.75,36.7 r270 bottom
R119 "RC0603FR-0710KL" RC0603#1 92.7,26.8 r180 bottom
R120 "RC0603FR-073KL" RC0603#1 109.7,32.55 r90 bottom
R121 "RC1206JR-072RL" RC1206 98.9,25 r0 bottom
R122 "RC1206JR-072RL" RC1206 98.9,27.35 r0 bottom
R123 "RC0603FR-0712K7L" RC0603#1 111.25,32.55 r90 bottom
R124 "RC0603FR-0710KL" RC0603#1 84.5,36.15 r180 top
R125 "RC0603FR-0710KL" RC0603#1 77,34.9 r180 top
R126 "RC0603FR-0752K3L" RC0603#1 84.5,37.7 r180 top
R127 "RC0603FR-0731K6L" RC0603#1 77,36.45 r180 top
R128 "RC0603JR-070RL" RC0603#1 107.85,13.35 r180 bottom
R129 "RC0805FR-072K7L" RC0805 109.6,13.35 r0 bottom
R130 "RC0603JR-070RL" RC0603#1 59.7,17.85 r180 top
REP1 "Comment" FIDICULAR_1X2MM 21,33.8 r0 top
REP2 "Comment" FIDICULAR_1X2MM 85.1,24.5 r0 top
REP3 "Comment" FIDICULAR_1X2MM 14.5,64.5 r0 top
REP4 "Comment" FIDICULAR_1X2MM 14.5,64.5 r180 bottom
REP5 "Comment" FIDICULAR_1X2MM 21,33.8 r180 bottom
REP6 "Comment" FIDICULAR_1X2MM 85.1,24.5 r180 bottom
RT1 "KTY82/110" SOT23 25.6,33.05 r0 bottom
RT2 "KTY81/110" TO-92-2s 29.4,39.95 r180 bottom
VD1 "NUP2105L" SOT-23#1 101.6,42.8 r270 bottom
VD2 "ES07D" DO-219AB(SMF) 59.8,42.35 r180 top
VD3 "ES07D" DO-219AB(SMF) 54.7,42.35 r180 top
VD4 "ES07D" DO-219AB(SMF) 49.55,42.35 r180 top
VD5 "UCLAMP3301D" SOD-323#1 84.95,61.8 r90 bottom
VD6 "UCLAMP3301D" SOD-323#1 73.35,23.6 r270 bottom
VD7 "BAV199-7-F" SOT23-3 61.7,65.95 r270 bottom
VD8 "BAV199-7-F" SOT23-3 57.85,65.95 r270 top
VD9 "BAV199-7-F" SOT23-3 61.65,65.95 r270 top
VD10 "BAV199-7-F" SOT23-3 65.45,65.95 r270 top
VD11 "BAV199-7-F" SOT23-3 57.8,65.95 r270 bottom
VD12 "BAV199-7-F" SOT23-3 76,53.85 r90 bottom
VD13 "BZT52-С3V9S" SOD-323#2 98.6,50.05 r270 top
VD14 "BZT52-С3V9S" SOD-323#2 98.6,51.3 r90 bottom
VD15 "BZT52-С3V9S" SOD-323#2 98.6,50 r270 bottom
VD16 "BZT52-С3V9S" SOD-323#2 101.6,56.35 r270 top
VD17 "BZT52-С3V9S" SOD-323#2 98.6,51.25 r90 top
VD18 "BZT52-С12S" SOD-323#2 110.4,10.1 r270 top
VD19 "ES07D" DO-219AB(SMF) 112.75,10.4 r270 top
VD20 "ES07D" DO-219AB(SMF) 113.05,31.95 r270 bottom
VD21 "ES07D" DO-219AB(SMF) 112.5,34.35 r270 top
VD22 "NSR0320MW2T1G" SOD-323#3 87.1,32.05 r90 top
VD23 "NSR0320MW2T1G" SOD-323#3 79.6,30.8 r90 top
VD24 "STTH1R02A" SMA/DO-214AC 101.8,22 r180 bottom
VD25 "STTH1R02A" SMA/DO-214AC 97,27.4 r0 top
VD26 "SMAJ12A" P4SMAJ18 107.05,10.5 r0 bottom
VT1 "AO3401A" SOT23 97.15,59.15 r180 top
VT2 "BC807-40" SOT-23#2 92.7,33.4 r180 bottom
VT3 "BC807-40" SOT-23#2 96.625,33.45 r0 top
VT4 "AO3401A" SOT23 96.6,31.55 r0 bottom
VT5 "AO3401A" SOT23 92.7,31.55 r180 top
VT6 "MMBT5551L" SOT-23#2 107.85,7.1 r180 bottom
VT7 "MMBT5551L" SOT-23#2 105.85,5.2 r90 top
VT8 "MMBT5551L" SOT-23#2 110.55,12.4 r90 top
VT9 "BC807-40" SOT-23#2 109.15,32.75 r270 top
VT10 "STN2NF10" SOT223 91.9,21.4 r0 bottom
X1 "Pad-AWG10" Pad-AWG10#1 5.9,27.85 r0 top
X2 "Pad-AWG10" Pad-AWG10#1 5.9,19.6 r0 top
X3 "Pad-AWG10" Pad-AWG10#1 5.9,44.2 r0 top
X4 "Pad-AWG10" Pad-AWG10#1 5.9,52.55 r0 top
X5 "Pad-AWG10" Pad-AWG10#2 5.9,60.8 r180 top
XP1 "8pin2mm" 8pin2mm 110.925,67.275 r270 top
XP2 "8pin2mm" 8pin2mm 105.75,53.275 r90 top
XP3 "8pin2mm" 8pin2mm 108.725,53.275 r90 top
XP4 "4pin2mm" 4pin2mm 113.125,53.275 r270 top
XP5 "6pin2mm" 6pin2mm 104.475,39.89 r270 top
XP6 "440055-6" 440055-6 108.725,44.9 r90 top
XV1 "PLS-1" PLS-1 75.82,66.45 r90 top
XV3 "PLS-1" PLS-1 80.9,66.45 r0 top
XV4 "PLS-1" PLS-1 73.28,66.45 r0 top
XV5 "Control Point" "Control Point" 77.45,55.75 r0 top
XV6 "Control Point" "Control Point" 78.95,55 r0 top
XV7 "PLS-1" PLS-1 68.2,66.45 r0 top
XV8 "PLS-1" PLS-1 83.44,66.45 r0 top
XV9 "PLS-1" PLS-1 85.98,66.45 r0 top
XV10 "PLS-1" PLS-1 70.74,66.45 r0 top

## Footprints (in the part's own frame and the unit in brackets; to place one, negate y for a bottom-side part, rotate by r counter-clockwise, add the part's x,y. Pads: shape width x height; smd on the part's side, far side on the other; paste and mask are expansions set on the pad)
4pin2mm [mm]
  rrect30% 1.25x1.25 hole 0.8 mask+0.1: 1(0,0)
  round 1.25 hole 0.8 mask+0.1: 2(-2,0) 3(-4,0) 4(-6,0)
6.3x11s [mm] "Through Hole Radial"
  rect 4x1.3 smd mask+0.1: 1(0,-1.25) 2(0,1.25)
  round 1.25 hole 0.8 mask+0.08: 1(0.5,-1.25) 2(0.5,1.25)
  Keep-Out Layer board cut-out: -16.5,3.85 -16.5,-3.85 -3,-3.85 -3,3.85
  body extent -16.01,-3.34 1.5,3.34, height 3.57
6pin2mm [mm]
  rrect30% 1.25x1.25 hole 0.8: 1(-0.01,1.3)
  round 1.25 hole 0.8: 2(-2.01,1.3) 3(-4.01,1.3) 4(-6.01,1.3) 5(-8.01,1.3) 6(-10.01,1.3)
8pin2mm [mm]
  rrect30% 1.25x1.25 hole 0.8 mask+0.1: 1(0,0)
  round 1.25 hole 0.8 mask+0.1: 2(2,0) 3(4,0) 4(6,0) 5(8,0) 6(10,0) 7(12,0) 8(14,0)
12.5x35s#1 [mm] "Through Hole Radial"
  round 1.25 hole 0.8 mask+0.08: 1(-0.65,0) 2(-0.65,5)
  rect 5x2 smd mask+0.1: 1(0,0) 2(0,5)
  Keep-Out Layer board cut-out: -42,9.25 -42,-4.25 -3.5,-4.25 -3.5,9.25
  body extent -41.51,-3.7 2,8.78, height 6.5
12.5x35s#2 [mm] "Through Hole Radial"
  round 1.25 hole 0.8 mask+0.08: 1(-0.65,0) 2(-0.65,-5)
  rect 5x2 smd mask+0.1: 1(0,0) 2(0,-5)
  Keep-Out Layer board cut-out: -42,-9.25 -42,4.25 -3.5,4.25 -3.5,-9.25
  body extent -41.51,-8.78 2,3.7, height 6.45
100A_05mmCUfoil [mm]
  rect 4x6.5 smd mask+0.08: 1(0,0) 2(12,0)
  silkscreen extent 3.97,-0.7 7.98,0.7, body extent -1.5,-3.01 13.5,3.01, height 0.55
0603 [mm] "Корпус 0603"
  rect 0.7x0.9 smd: 1(0,0) 2(1.5,0)
  silkscreen extent 0.63,-0.45 0.88,0.45, body extent -0.05,-0.4 1.55,0.4, height 0.8
0805 [mm] "Корпус 0805"
  rect 0.8x1.4 smd: 1(0,0) 2(1.9,0)
  silkscreen extent 0.75,-0.63 1.15,0.61, body extent -0.05,-0.63 1.95,0.63, height 1.25
1206 [mm] "Корпус 1206"
  rect 1.1x1.7 smd: 1(0,0) 2(3,0)
  silkscreen extent 0.95,-0.8 2.05,0.8, body extent -0.1,-0.8 3.1,0.8, height 1.6
1210 [mm] "Корпус 1210"
  rect 1.1x2.7 smd: 1(0,0) 2(3,0)
  silkscreen extent 0.87,-1.3 2.12,1.3, body extent -0.1,-1.3 3.1,1.3, height 2.5
440055-6 [mm] "6 pins Header Right Angle"
  rrect30% 1.25x1.25 hole 0.8 mask+0.08: 1(-5,0)
  round 1.25 hole 0.8 mask+0.08: 2(-3,0) 3(-1,0) 4(1,0) 5(3,0) 6(5,0)
  silkscreen extent -7.05,-6.3 7.05,1.5, body extent -7,-6.25 7,1.45, height 4.97
BLM18 [mm] "Корпус 0603"
  rect 0.7x0.9 smd: 1(0,0) 2(1.5,0)
  silkscreen extent 0.65,-0.45 0.85,0.45, body extent -0.1,-0.45 1.6,0.45, height 0.8
"Control Point" [mm]
  round 0.9 hole 0.4 mask+0.08: 1(0,0)
  silkscreen extent -0.75,-0.75 0.75,0.75
CRE2512 [mm] "3W"
  rect 3.2x3.8 smd: 1(0,0) 2(4.8,0)
  silkscreen extent -1.88,-2.17 6.68,2.17, body extent -0.85,-1.7 5.65,1.7, height 0.7
DLW21S [mm] "3.2x1.6"
  rect 0.9x0.4 smd paste+0 mask+0.08: 1(-0.85,-0.425) 2(0.85,-0.425) 3(0.85,0.425) 4(-0.85,0.425)
  silkscreen extent -0.13,-0.67 0.13,0.67, body extent -1,-0.6 1,0.6, height 1.2
DO-219AB(SMF) [mm] "DO-219AB (SMF) (SOD-123FL)"
  rrect30% 1.1x1.3 smd mask+0.08: 1(0,0) 2(3.1,0)
  silkscreen extent 0.15,-1 2.95,1, body extent 0.15,-0.9 2.95,0.9, height 1
FIDICULAR_1X2MM [mm] "Fidicular Mark"
  round 1 smd mask+0.5: 0(0,0)
  Top Layer pour cut-out: 0,-1 -0.383,-0.924 -0.707,-0.707 -0.924,-0.383 -1,0 -1,0 -0.924,0.383 -0.707,0.707 -0.383,0.924 0,1 0,1 0.383,0.924 0.707,0.707 0.924,0.383 1,0 1,0 0.924,-0.383 0.707,-0.707 0.383,-0.924 0,-1
  silkscreen extent -1.1,-1.1 1.1,1.1, body extent -1.01,-1.01 1.01,1.01, height 0.02
HL0603 [mm]
  rect 0.7x0.9 smd: 1(0,0) 2(1.6,0)
  silkscreen extent -0.65,-0.47 0.97,0.48, body extent -0.05,-0.45 1.65,0.45, height 0.6
ISOPLUS-DIL [mm]
  round 3.4 hole 3.4 unplated mask+0.08: 0(0,-21) 0(0,21)
  rect 9x4.8 smd: 1(-16.9,15) 2(-16.9,9) 4(-16.9,-3) 5(-16.9,-9) 6(-16.9,-15)
  rrect30% 8x1.5 smd: 7(16.9,-16.5) 8(16.9,-13.5) 9(16.9,-10.5) 10(16.9,-7.5) 11(16.9,-4.5) 12(16.9,-1.5) 13(16.9,1.5) 14(16.9,4.5) 15(16.9,7.5) 16(16.9,10.5) 17(16.9,13.5) 18(16.9,16.5)
  Bottom Layer pour cut-out: 0,-25.5 -1.722,-25.157 -3.182,-24.182 -4.157,-22.722 -4.5,-21 -4.5,-21 -4.157,-19.278 -3.182,-17.818 -1.722,-16.843 0,-16.5 0,-16.5 1.722,-16.843 3.182,-17.818 4.157,-19.278 4.5,-21 4.5,-21 4.157,-22.722 3.182,-24.182 1.722,-25.157 0,-25.5
  Bottom Layer pour cut-out: 0,16.5 -1.722,16.843 -3.182,17.818 -4.157,19.278 -4.5,21 -4.5,21 -4.157,22.722 -3.182,24.182 -1.722,25.157 0,25.5 0,25.5 1.722,25.157 3.182,24.182 4.157,22.722 4.5,21 4.5,21 4.157,19.278 3.182,17.818 1.722,16.843 0,16.5
  body extent -19.15,-18.75 19.78,18.75, height 5.02
IZM1 [mm]
  silkscreen extent 0,0 7.3,3.8
LQFP-64 [mm]
  rect 1.2x0.25 smd mask+0.05: 1(-5.75,3.75) 2(-5.75,3.25) 3(-5.75,2.75) 4(-5.75,2.25) 5(-5.75,1.75) 6(-5.75,1.25) 7(-5.75,0.75) 8(-5.75,0.25) 9(-5.75,-0.25) 10(-5.75,-0.75) 11(-5.75,-1.25) 12(-5.75,-1.75) 13(-5.75,-2.25) 14(-5.75,-2.75) 15(-5.75,-3.25) 16(-5.75,-3.75) 33(5.75,-3.75) 34(5.75,-3.25) 35(5.75,-2.75) 36(5.75,-2.25) 37(5.75,-1.75) 38(5.75,-1.25) 39(5.75,-0.75) 40(5.75,-0.25) 41(5.75,0.25) 42(5.75,0.75) 43(5.75,1.25) 44(5.75,1.75) 45(5.75,2.25) 46(5.75,2.75) 47(5.75,3.25) 48(5.75,3.75)
  rect 0.25x1.2 smd mask+0.05: 17(-3.75,-5.75) 18(-3.25,-5.75) 19(-2.75,-5.75) 20(-2.25,-5.75) 21(-1.75,-5.75) 22(-1.25,-5.75) 23(-0.75,-5.75) 24(-0.25,-5.75) 25(0.25,-5.75) 26(0.75,-5.75) 27(1.25,-5.75) 28(1.75,-5.75) 29(2.25,-5.75) 30(2.75,-5.75) 31(3.25,-5.75) 32(3.75,-5.75) 49(3.75,5.75) 50(3.25,5.75) 51(2.75,5.75) 52(2.25,5.75) 53(1.75,5.75) 54(1.25,5.75) 55(0.75,5.75) 56(0.25,5.75) 57(-0.25,5.75) 58(-0.75,5.75) 59(-1.25,5.75) 60(-1.75,5.75) 61(-2.25,5.75) 62(-2.75,5.75) 63(-3.25,5.75) 64(-3.75,5.75)
  silkscreen extent -5.9,-5 5,5, body extent -6,-6 6,6, height 1.4
"LR 7-pin PSOF" [mm] "LR 7-pin PSOF"
  rect 0.6x1.8 smd: 1(-1.6,-2.6) 2(0,-2.6) 3(1.6,-2.6)
  rect 1.1x0.6 smd: 4(2.9,0) 7(-2.9,0)
  rect 2.2x1.9 smd: 5(1.55,2.45) 6(-1.55,2.45)
  silkscreen extent -3.2,-3.27 3.2,2.4, body extent -3.2,-3.2 3.2,3.2, height 1.5
MJ-series [mm] "5x3.2x1"
  rrect30% 1.9x1.2 smd paste+0 mask+0.08: 1(0,0) 2(-3.7,0) 3(-3.7,2.2) 4(0,2.2)
  silkscreen extent -4.35,-0.5 1.55,2.7, body extent -4.35,-0.5 0.65,2.7, height 0.9
P4SMAJ18 [mm]
  rect 2.25x2.06 smd mask+0.1: 1(0,0) 2(4,0)
  silkscreen extent -0.48,-1.5 4.3,1.5, body extent -0.3,-1.45 4.3,1.45, height 2.45
Pad-AWG10#1 [mm] "Pad for solder wire AWG10"
  round 0.9 hole 0.4 mask+0.08: 1(-3.75,-1.4) 1(-3.75,1.4) 1(-3,-2.8) 1(-3,0) 1(-3,2.8) 1(-2.25,-1.4) 1(-2.25,1.4) 1(-1.5,-2.8) 1(-1.5,2.8) 1(1.5,-2.8) 1(1.5,2.8) 1(2.25,-1.4) 1(2.25,1.4) 1(3,-2.8) 1(3,0) 1(3,2.8) 1(3.75,-1.4) 1(3.75,1.4)
  rect 9x6.5 smd: 1(0,0)
  round 6.5 hole 4 mask+0.08: 1(0,0)
  silkscreen extent -4.95,-3.7 4.95,3.7
Pad-AWG10#2 [mm] "Pad for solder wire AWG10"
  round 0.9 hole 0.4 mask+0.08: 1(-3.75,-1.4) 1(-3.75,1.4) 1(-3,2.8) 1(-3,0) 1(-3,-2.8) 1(-2.25,-1.4) 1(-2.25,1.4) 1(-1.5,2.8) 1(-1.5,-2.8) 1(1.5,2.8) 1(1.5,-2.8) 1(2.25,-1.4) 1(2.25,1.4) 1(3,2.8) 1(3,0) 1(3,-2.8) 1(3.75,-1.4) 1(3.75,1.4)
  rect 9x6.5 smd: 1(0,0)
  round 6.5 hole 4: 1(0,0)
  silkscreen extent -4.95,-3.7 4.95,3.7
PLS-1 [mm]
  round 1.6 hole 1 mask+0.1: 1(0,0)
  silkscreen extent -1.35,-1.35 1.35,1.35
RC0603#1 [mm]
  rect 0.7x0.9 smd: 1(0,0) 2(1.5,0)
  silkscreen extent 0.63,-0.53 0.88,0.53, body extent -0.1,-0.45 1.6,0.45, height 0.5
RC0603#2 [mm]
  rrect30% 0.7x0.9 smd: 1(0,0) 2(1.5,0)
  silkscreen extent 0.63,-0.53 0.88,0.53, body extent -0.1,-0.45 1.6,0.45, height 0.5
RC0805 [mm]
  rect 0.8x1.4 smd paste+0 mask+0.1: 1(0,0) 2(2,0)
  silkscreen extent 0.67,-0.72 1.33,0.72, body extent 0,-0.63 2,0.63, height 0.5
RC1206 [mm]
  rect 1.3x1.8 smd: 1(0,0) 2(2.9,0)
  silkscreen extent 0.97,-0.92 1.92,0.92, body extent -0.2,-0.82 3.1,0.82, height 0.55
SH3018 [mm]
  rrect50% 0.5x4.3 smd mask+0.075: 1(-1.9,0) 2(1.9,0)
  rect 1.3x0.5 smd mask+0.075: 1(-1.2,-1.9) 1(-1.2,1.9) 2(1.2,-1.9) 2(1.2,1.9)
  Top Layer region: -0.55,1.179 -0.552,1.179 -0.552,1.179 -0.552,1.179 -0.656,1.136 -0.927,0.927 -1.136,0.656 -1.267,0.339 -1.311,0 -1.267,-0.339 -1.136,-0.656 -0.927,-0.927 -0.656,-1.136 -0.552,-1.179 -0.552,-1.179 -0.552,-1.179 -0.55,-1.179 -0.55,-1.9 -1.9,-1.9 -1.9,1.9 -0.55,1.9
  Top Layer region: 0.55,-1.179 0.552,-1.179 0.552,-1.179 0.552,-1.179 0.656,-1.136 0.927,-0.927 1.136,-0.656 1.267,-0.339 1.311,0 1.267,0.339 1.136,0.656 0.927,0.927 0.656,1.136 0.552,1.179 0.552,1.179 0.552,1.179 0.55,1.179 0.55,1.9 1.9,1.9 1.9,-1.9 0.55,-1.9
  Keep-Out Layer lines w0.1: -0.091,-1.9 -0.091,-0.744 cw(c0,0) -0.091,0.744 -0.091,1.9 0.091,1.9 0.091,0.744 cw(c0,0) 0.091,-0.744 0.091,-1.9 -0.091,-1.9
  Multi-Layer pour cut-out: -0.528,-1.133 -0.971,-0.787 -1.218,-0.281 -1.218,0.281 -0.971,0.787 -0.528,1.133 -0.528,1.133 -0.528,2.15 0.528,2.15 0.528,1.133 0.971,0.787 1.218,0.281 1.218,-0.281 0.971,-0.787 0.528,-1.133 0.528,-1.133 0.528,-2.15 -0.528,-2.15
  silkscreen extent -0.9,-2.07 0.9,2.07, body extent -1.9,-1.9 1.9,1.9, height 1.8
SMA/DO-214AC [mm]
  rect 2.5x1.8 smd mask+0.08: 1(0,0)
  rect 2.5x1.8 smd: 2(4,0)
  silkscreen extent -0.4,-1.5 4.4,1.5, body extent -0.35,-1.45 4.35,1.45, height 2.5
SOD-323#1 [mm]
  rect 1.3x0.7 smd: 1(0,0) 2(2.1,0)
  silkscreen extent -0.95,-0.77 1.95,0.8, body extent 0.15,-0.7 1.95,0.7, height 1.1
SOD-323#2 [mm]
  rect 0.65x1 smd: 1(0,0) 2(2.4,0)
  silkscreen extent 0.3,-0.77 2.1,0.78, body extent 0.3,-0.7 2.1,0.7, height 1.1
SOD-323#3 [mm]
  rect 0.7x1 smd mask+0.08: 1(0,0) 2(2.3,0)
  silkscreen extent 0.25,-0.77 2.05,0.77, body extent 0.25,-0.7 2.05,0.7, height 1.1
SOIC-8 [mm] "Drawing D (R-PDSO-G8)"
  rrect50% 1.6x0.6 smd: 1(0,0) 2(0,-1.27) 3(0,-2.54) 4(0,-3.81) 5(5.4,-3.81) 6(5.4,-2.54) 7(5.4,-1.27) 8(5.4,0)
  silkscreen extent 0.18,-4.5 4.25,0.9, body extent 0.7,-4.4 4.7,0.59, height 1.75
SOIC-14N [mm] "SOIC_N(R-14)"
  rrect50% 1.6x0.6 smd: 1(0,0) 2(0,-1.27) 3(0,-2.54) 4(0,-3.81) 5(0,-5.08) 6(0,-6.35) 7(0,-7.62) 8(5.4,-7.62) 9(5.4,-6.35) 10(5.4,-5.08) 11(5.4,-3.81) 12(5.4,-2.54) 13(5.4,-1.27) 14(5.4,0)
  silkscreen extent -0.22,-8.31 4.25,0.98, body extent 0.7,-8.21 4.7,0.59, height 1.75
SOIC-28 [mm] "SOIC, 28-Leads, Body 17.9x7.5mm, Pitch 1.27mm, IPC High Density"
  rrect30% 2x0.6 smd: 1(-4.7,8.255) 2(-4.7,6.985) 3(-4.7,5.715) 4(-4.7,4.445) 5(-4.7,3.175) 6(-4.7,1.905) 7(-4.7,0.635) 8(-4.7,-0.635) 9(-4.7,-1.905) 10(-4.7,-3.175) 11(-4.7,-4.445) 12(-4.7,-5.715) 13(-4.7,-6.985) 14(-4.7,-8.255) 15(4.7,-8.255) 16(4.7,-6.985) 17(4.7,-5.715) 18(4.7,-4.445) 19(4.7,-3.175) 20(4.7,-1.905) 21(4.7,-0.635) 22(4.7,0.635) 23(4.7,1.905) 24(4.7,3.175) 25(4.7,4.445) 26(4.7,5.715) 27(4.7,6.985) 28(4.7,8.255)
  silkscreen extent -5.32,-9.05 3.1,9.25, body extent -3.8,-9.06 3.8,9.06, height 2.65
SOP-8 [mm]
  rrect50% 1.6x0.6 smd: 1(0,0) 2(0,-1.27) 3(0,-2.54) 4(0,-3.81) 5(5.4,-3.81) 6(5.4,-2.54) 7(5.4,-1.27) 8(5.4,0)
  silkscreen extent -0.22,-4.5 4.25,0.97, body extent 0.7,-4.4 4.7,0.59, height 1.75
SOT23 [mm] "Корпус SOT23"
  rect 1x0.8 smd mask+0.1: 1(0,0) 2(0,-1.9) 3(2,-0.95)
  silkscreen extent -0.25,-2.45 1.7,0.92, body extent 0.3,-2.45 1.7,0.55, height 1.1
SOT23-3 [mm] "Корпус SOT23"
  rect 1x0.8 smd mask+0.1: 1(0,0) 2(0,-1.9) 3(2,-0.95)
  silkscreen extent -0.3,-2.45 1.7,0.92, body extent 0.3,-2.45 1.7,0.55, height 1.1
SOT23-5 [mm] "Корпус 5 SOT23"
  rect 1x0.6 smd mask+0.08: 1(0,0) 2(0,-0.95) 3(0,-1.9) 4(2.7,-1.9) 5(2.7,0)
  silkscreen extent -0.17,-2.55 1.88,0.82, body extent 0.48,-2.45 2.22,0.55, height 1.45
SOT23-6 [mm] "Корпус 6 SOT23"
  rect 1x0.6 smd mask+0.08: 1(0,0) 2(0,-0.95) 3(0,-1.9) 4(2.7,-1.9) 5(2.7,-0.95) 6(2.7,0)
  silkscreen extent -1.1,-2.45 1.88,0.55, body extent 0.48,-2.45 2.22,0.55, height 1.45
SOT223 [mm]
  rrect30% 1.2x2 smd mask+0.08: 1(-2.3,-3) 2(0,-3) 3(2.3,-3)
  rrect30% 3.3x2 smd mask+0.08: 2(-0.025,3)
  silkscreen extent -3.6,-3.12 3.35,1.4, body extent -3.35,-1.85 3.35,1.85, height 1.65
SOT-23#1 [mm] "Корпус SOT23"
  rect 1x0.8 smd mask+0.08: 1(0,0) 2(0,-1.9) 3(2,-0.95)
  silkscreen extent -0.4,-2.45 1.7,0.92, body extent 0.3,-2.45 1.7,0.55, height 1.1
SOT-23#2 [mm] "Корпус SOT23"
  rect 1x0.8 smd mask+0.1: 1(0,0) 2(0,-1.9) 3(2,-0.95)
  silkscreen extent -0.4,-2.45 1.7,0.92, body extent 0.3,-2.45 1.7,0.55, height 1.1
SRR1050A [mm] "10x10x5"
  rrect20% 2.4x4.2 smd: 1(-4.6,0) 2(4.6,0)
  silkscreen extent -5.1,-5.1 5.1,5.1, body extent -5.1,-5 5.1,5.01, height 5.05
TO-92-2s [mm] "Плоская грань на расстоянии 5мм от платы"
  oval 1.8x1.1 hole 0.8: 1(0,1.27) 2(0,-1.27)
  silkscreen extent -7.72,-2.4 -1.25,2.4, body extent -7.72,-2.4 0.22,2.4, height 5

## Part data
A1: "IGBT-modules"
BQ1: library part MJ-16.000-16P, "Кварцевый резонатор"
C1 C2 C3 C16 C21 C27 C28 C29 C30 C33 C37 C41 C47 C70 C71 C73 C83: "0603 - 50V - 0,1uF"
C4 C5 C7 C8 C35 C36: "0603 - 50V - 12pF"
C6 C31 C32 C34 C78: library part CL10A225KP8NNNC, "0603, 10V, 2.2uF"
C9 C10 C87 C88: "1206, 25V, 10uF"
C11 C38 C39 C45 C46 C65 C66 C67 C68 C69: library part CL10B103KB8NNNC, "0603 - 50V - 0,01uF"
C12 C13 C14: "0805, 25V, 4.7uF"
C15 C23 C25 C26 C48 C49 C50 C51 C52 C53 C54 C55 C56 C57 C59 C60 C63 C64 C81 C82: "0603 - 50V - 0,01uF"
C17 C18 C19 C20 C74: library part CL32B106KBJNNNE, "1210 - 100V - 2,2uF"
C22 C24: "12.5x35 100V 390uF Low impedance Aluminum Capacitor"
C40 C42 C43: library part CL10C120JB8NNNC, "0603 - 50V - 12pF"
C44 C75 C79 C80: library part CL10C151JB8NNNC, "0603 - 50V - 150pF"
C58 C61 C62: library part CL10B104KB8NNNC, "0603 - 50V - 0,1uF"
C72 C76 C77: library part CL31B104KCFNNNE, "1206, 100V, 0.1uF"
C84 C85: library part CL31B226KPHNNNE, "1206, 16V, 22uF"
C86: "6.3x11 25V 100uF High Ripple Current Al. Cap."
D1: "Dual Buffer Gate"
D2: "0.9 Ohm SPST ANALOG SWITCH"
D3: "EMC OPTIMIZED CAN TRANSCEIVER"
D4: "3-Phase Half-Bridge Gate-Drive IC"
D5 D6: "High-Precision Current Sensor IC"
D7: library part STM32F303RCT6, "ARM Cortex-M4 32-b MCU+FPU with 256 KB Flash, CAN, 4 ADCs, 7 comp, 4PGA"
D8: "Precision Low Noise CMOS Rail-to-Rail OpAmp"
D9: "Current-Mode PWM Controller"
D10 D11: "4.5 V to 18 V Input, 1.4MHz, 1.5A DC-DC Buck Converter"
FU1: library part 100A_05mmCU, "100A предохранитель из фольги 0,5мм"
HL1: library part BL-HGF36A-AV-TRB, "Surface Mount LED"
HL2: "Surface Mount LED"
L1: "Chip Common Mode Choke Coil"
L2 L4 L5 L6 L7 L8 L9: "EMI Suppression Filter"
L3: library part BLM18AG601SN1D, "EMI Suppression Filter"
L10 L11: "Катушка индуктивности"
L12: library part SRR1050A, "Катушка индуктивности"
R1 R2 R3 R4 R5 R6 R7 R8 R9 R10 R11 R12 R13 R14 R15 R16 R17 R21 R23 R24 R25 R26 R27 R28 R29 R30 R31 R32 R33 R34 R35 R36 R37 R38 R39 R40 R41 R42 R43 R44 R45 R46 R47 R55 R57 R58 R59 R60 R61 R62 R63 R64 R65 R66 R67 R68 R69 R70 R71 R72 R73 R74 R75 R76 R77 R78 R79 R80 R81 R82 R83 R84 R85 R86 R87 R88 R89 R90 R91 R92 R93 R94 R95 R98 R99 R100 R101 R102 R103 R104 R105 R106 R107 R109 R113 R114 R115 R116 R117 R118 R119 R120 R123 R124 R125 R126 R127 R128 R130: library part RC0603, "0603, 0.1W, Thick Film Chip Resistors"
R18 R19 R20 R22: library part CRE2512, "Resistor, Bourns"
R48 R49 R50 R96 R97 R121 R122: library part RC1206, "1206, 0.25W, Thick Film Chip Resistors"
R51 R52 R53 R54 R56 R108 R110 R111 R112 R129: library part RC0805, "0805, 0.125W, Thick Film Chip Resistors"
RT1: library part KTY82/110.215, "Silicon temperature sensors"
RT2: library part KTY81/110,112, "Silicon temperature sensors"
VD1: "SURFACE MOUNT SWITCHING DIODES"
VD2 VD3 VD4 VD19 VD20 VD21: "Ultrafast Rectifier"
VD5 VD6: "Transient Volnage Supressor Power 100 W"
VD7 VD8 VD9 VD10 VD11 VD12: library part BAV199, "DUAL SURFACE MOUNT LOW LEAKAGE DIODE"
VD13 VD14 VD15 VD16 VD17 VD18: library part BZT52, "SURFACE Stabilitron"
VD22 VD23: library part NSR0320MW2T1, "20V 1A Schottky Barrier Diodes"
VD24 VD25: "Ultrafast recovery diode"
VD26: library part P4SMAJ18, "Transient Volnage Supressor Power 400 W"
VT1 VT4 VT5: "-30V P-Channel MOSFET"
VT2 VT3 VT9: "45 V, 500 mA PNP general-purpose transistor"
VT6 VT7 VT8: "300V NPN High Voltage Transistors"
VT10: library part DMN10H120SE, "100V N-Channel MOSFET"
X1 X2 X3 X4 X5: "Площадка для запайки провода AWG10"
XP1 XP2 XP3: "Вилка на плату 8 контактов"
XP4: "Вилка на плату 4 контакта"
XP5: "Вилка на плату 6 контактов"
XP6: "Вилка уголовая на плату 6 контактов"
XV1 XV3 XV4 XV7 XV8 XV9 XV10: library part DS1021-1x1, "Вилка PLS"
XV5 XV6: "Контрольная точка с отверстием"

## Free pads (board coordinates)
  round 3.4 hole 3.4 unplated mask+0.08: 0(13,36)
  rect 4x6.5 smd: 0(20.9,27.85)

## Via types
v1: diameter 0.9, hole 0.4, Top Layer to Bottom Layer, 233 vias
v2: diameter 0.7, hole 0.3, Top Layer to Bottom Layer, tented both sides, 184 vias
v3: diameter 0.9, hole 0.4, Top Layer to Bottom Layer, tented both sides, 50 vias
v4: diameter 0.9, hole 0.4, Top Layer to Bottom Layer, tented bottom, 25 vias

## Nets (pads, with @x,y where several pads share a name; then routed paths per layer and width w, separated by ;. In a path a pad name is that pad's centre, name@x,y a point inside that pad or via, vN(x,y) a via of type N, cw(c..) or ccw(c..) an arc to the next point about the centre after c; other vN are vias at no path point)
1V65RF: C40.2 D8.6 D8.7 R38.1 | length 6.1
  Top Layer w0.25: D8.7@67.93,23.55 67.93,25.43 C40.2@67.95,25.45 ; R38.1@67.95,26.95 C40.2@67.95,25.45 ; D8.6@69.2,23.55 69.2,24.65 68.7,25.15 68.25,25.15 C40.2@67.95,25.45
3V3A: C16.2 C21.2 C33.2 C34.2 C47.2 D5.1 D6.1 D7.13 D8.4 L3.2 R40.1 R55.2 R79.2 R80.2 VD6.1 VD7.2 VD8.2 VD9.2 VD10.2 VD11.2 VD12.2 VT1.2 | length 207.2
  Top Layer w0.25: C21.2@19.15,37 D6.1@19.15,38.9 ; C16.2@19.15,65.6 v2(19.15,66.6) ; VD8.2@55.95,65.95 v2(55.95,67.5) ; VD9.2@59.75,65.95 v2(59.75,67.5) ; VD10.2@63.55,65.95 v2(63.55,67.5) ; R40.1@71.7,25.15 72.3,25.15 v2(72.4,25.05) 72.4,24.65 71.74,23.99 D8.4@71.74,23.55 ; v2(74.25,56.9) R80.2@74.25,57.85 ; D7.13@82.2,54.25 v2(82.2,55.85) ; v2(95.9,61.15) 97.05,61.15 VT1.2@97.15,61.05
  Top Layer w0.35: v3(18.1,36.95) C21.2@19.2,36.95
  Mid-Layer 1 w0.35: v3(18.1,36.95) 24.55,36.95 27.4,39.8 30.9,39.8 31.6,39.1 36.3,39.1 37.45,40.25 56.851,40.25 63.301,33.8 72.4,33.8 76.5,37.9 76.5,38.75 78.715,40.965 v2@78.715,41.635
  Mid-Layer 2 w0.25: v2(55.95,67.5) 55.95,68.95 ; v2(59.75,67.5) 59.75,68.95 ; v2(63.55,67.5) 63.55,68.95
  Mid-Layer 2 w0.35: v2(19.15,66.6) 21.5,68.95 55.95,68.95 59.75,68.95 63.55,68.95 103.15,68.95 103.85,68.25 103.85,62.65 v2(104.525,61.975)
  Bottom Layer w0.25: D5.1@19.15,65.1 v2(19.15,66.6) ; VD11.2@59.75,65.95 v2(59.75,67.5) ; VD7.2@63.55,65.95 v2(63.55,67.5) ; C47.2@71.7,23.3 72.4,24 72.8,23.6 VD6.1@73.35,23.6 ; VD12.2@74.25,54 v2(74.25,56.9) ; C34.2@77.3,40.05 L3.2@78.6,40.05 ; L3.2@78.7,39.95 v2(78.7,41.65) ; R55.2@80.8,56.4 81.65,56.4 v2(82.2,55.85) 82.2,55.05 C33.2@82.3,54.95 ; v2(95.9,61.15) 97.825,61.15 98.05,61.375 101.85,61.375 ; R79.2@101.85,60.6 101.85,61.375 ; v2(104.525,61.975) 104.525,61.909 103.991,61.375 101.85,61.375
  Bottom Layer w0.35: 72.4,24 v2(72.4,25.05)
3V3D: C1.2 C27.2 C28.2 C29.2 C30.2 C31.2 C32.2 C85.2 D1.5 D4.10 D7.1 D7.19 D7.32 D7.48 D7.64 D10.4 L2.1 L3.1 L11.2 R4.1 R29.2 R30.2 R127.1 XP6.1 | length 130.5
  Top Layer w0.25: D4.10@47.725,56.35 47.725,57.775 48.25,58.3 R4.1@48.25,58.4 R4.1@48.25,58.5 ; R127.1@77,36.15 80.4,36.15 81.35,35.2 v3@81.35,31.6 ; v2(77.05,51.05) 77.25,51.25 D7.19@78.7,51.25 ; v2(77.95,43.95) 77.95,44.6 78.1,44.75 D7.32@78.7,44.75 ; 81.95,32 D10.4@83.3,32 ; D7.48@88.2,42.75 88.2,42.3 88.5,42 88.75,42 89.4,41.35 C29.2@89.4,41.25 89.35,41.2 v2(89.35,40.2) ; D7.1@88.2,54.25 88.2,54.775 88.45,55.025 88.7,55.025 89.25,55.575 C32.2@89.25,55.7 ; C32.2@89.15,55.7 C32.2@89.25,55.7 ; v2(89.25,56.75) C32.2@89.25,55.7 ; R30.2@89.7,65.8 89.7,65.7 90.475,64.925 90.475,63.275 v2(91,62.75) ; D7.64@90.2,52.25 90.65,52.25 91.6,53.2 C30.2@91.7,53.2 ; C30.2@91.7,53.25 v2(92.75,53.25) ; R29.2@94.7,53.7 v2(95.75,53.7) ; v2(97.65,37.85) 98.15,37.85 98.8,37.2 98.8,36.7 D1.5@98.95,36.55
  Top Layer w0.35: D4.10@47.725,56.35 47.725,55.575 48.6,54.7 51.25,54.7 53.65,52.3 64.25,52.3 66.65,54.7 69,54.7 69.9,53.8 69.9,48.2 68.95,47.25 68.95,40.75 72.2,37.5 v2(78.7,37.5) ; v2(91.55,38.9) 91.875,39.225 96.275,39.225 v2(97.65,37.85)
  Bottom Layer w0.25: v2@77.05,50.9 C27.2@77.7,50.9 ; v2(77.95,43.95) C28.2@77.95,45 ; C27.2@78,50.6 C27.2@78,50.7 ; v2(78.7,37.5) L3.1@78.7,38.45 ; v2(89.35,40.2) C31.2@89.35,41.25 ; 97.575,44.575 101.825,44.575 v2(101.9,44.5) ; v2(97.65,37.85) 98.1,38.3 C1.2@98.6,38.3
  Bottom Layer w0.35: C85.2@79.4,30.6 C85.2@79.4,30.95 ; v2(90.85,41.65) 95.75,41.65 96.85,42.75 96.85,43.85 97.575,44.575 ; v2(97.65,37.85) 98.4,37.1 100.6,37.1 102.212,38.713 107.538,38.713 XP6.1@108.725,39.9 110.175,41.35 110.175,47.85 111.275,48.95 L2.1@111.275,50.15
  other v3: 81,30.4 81.6,31.35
